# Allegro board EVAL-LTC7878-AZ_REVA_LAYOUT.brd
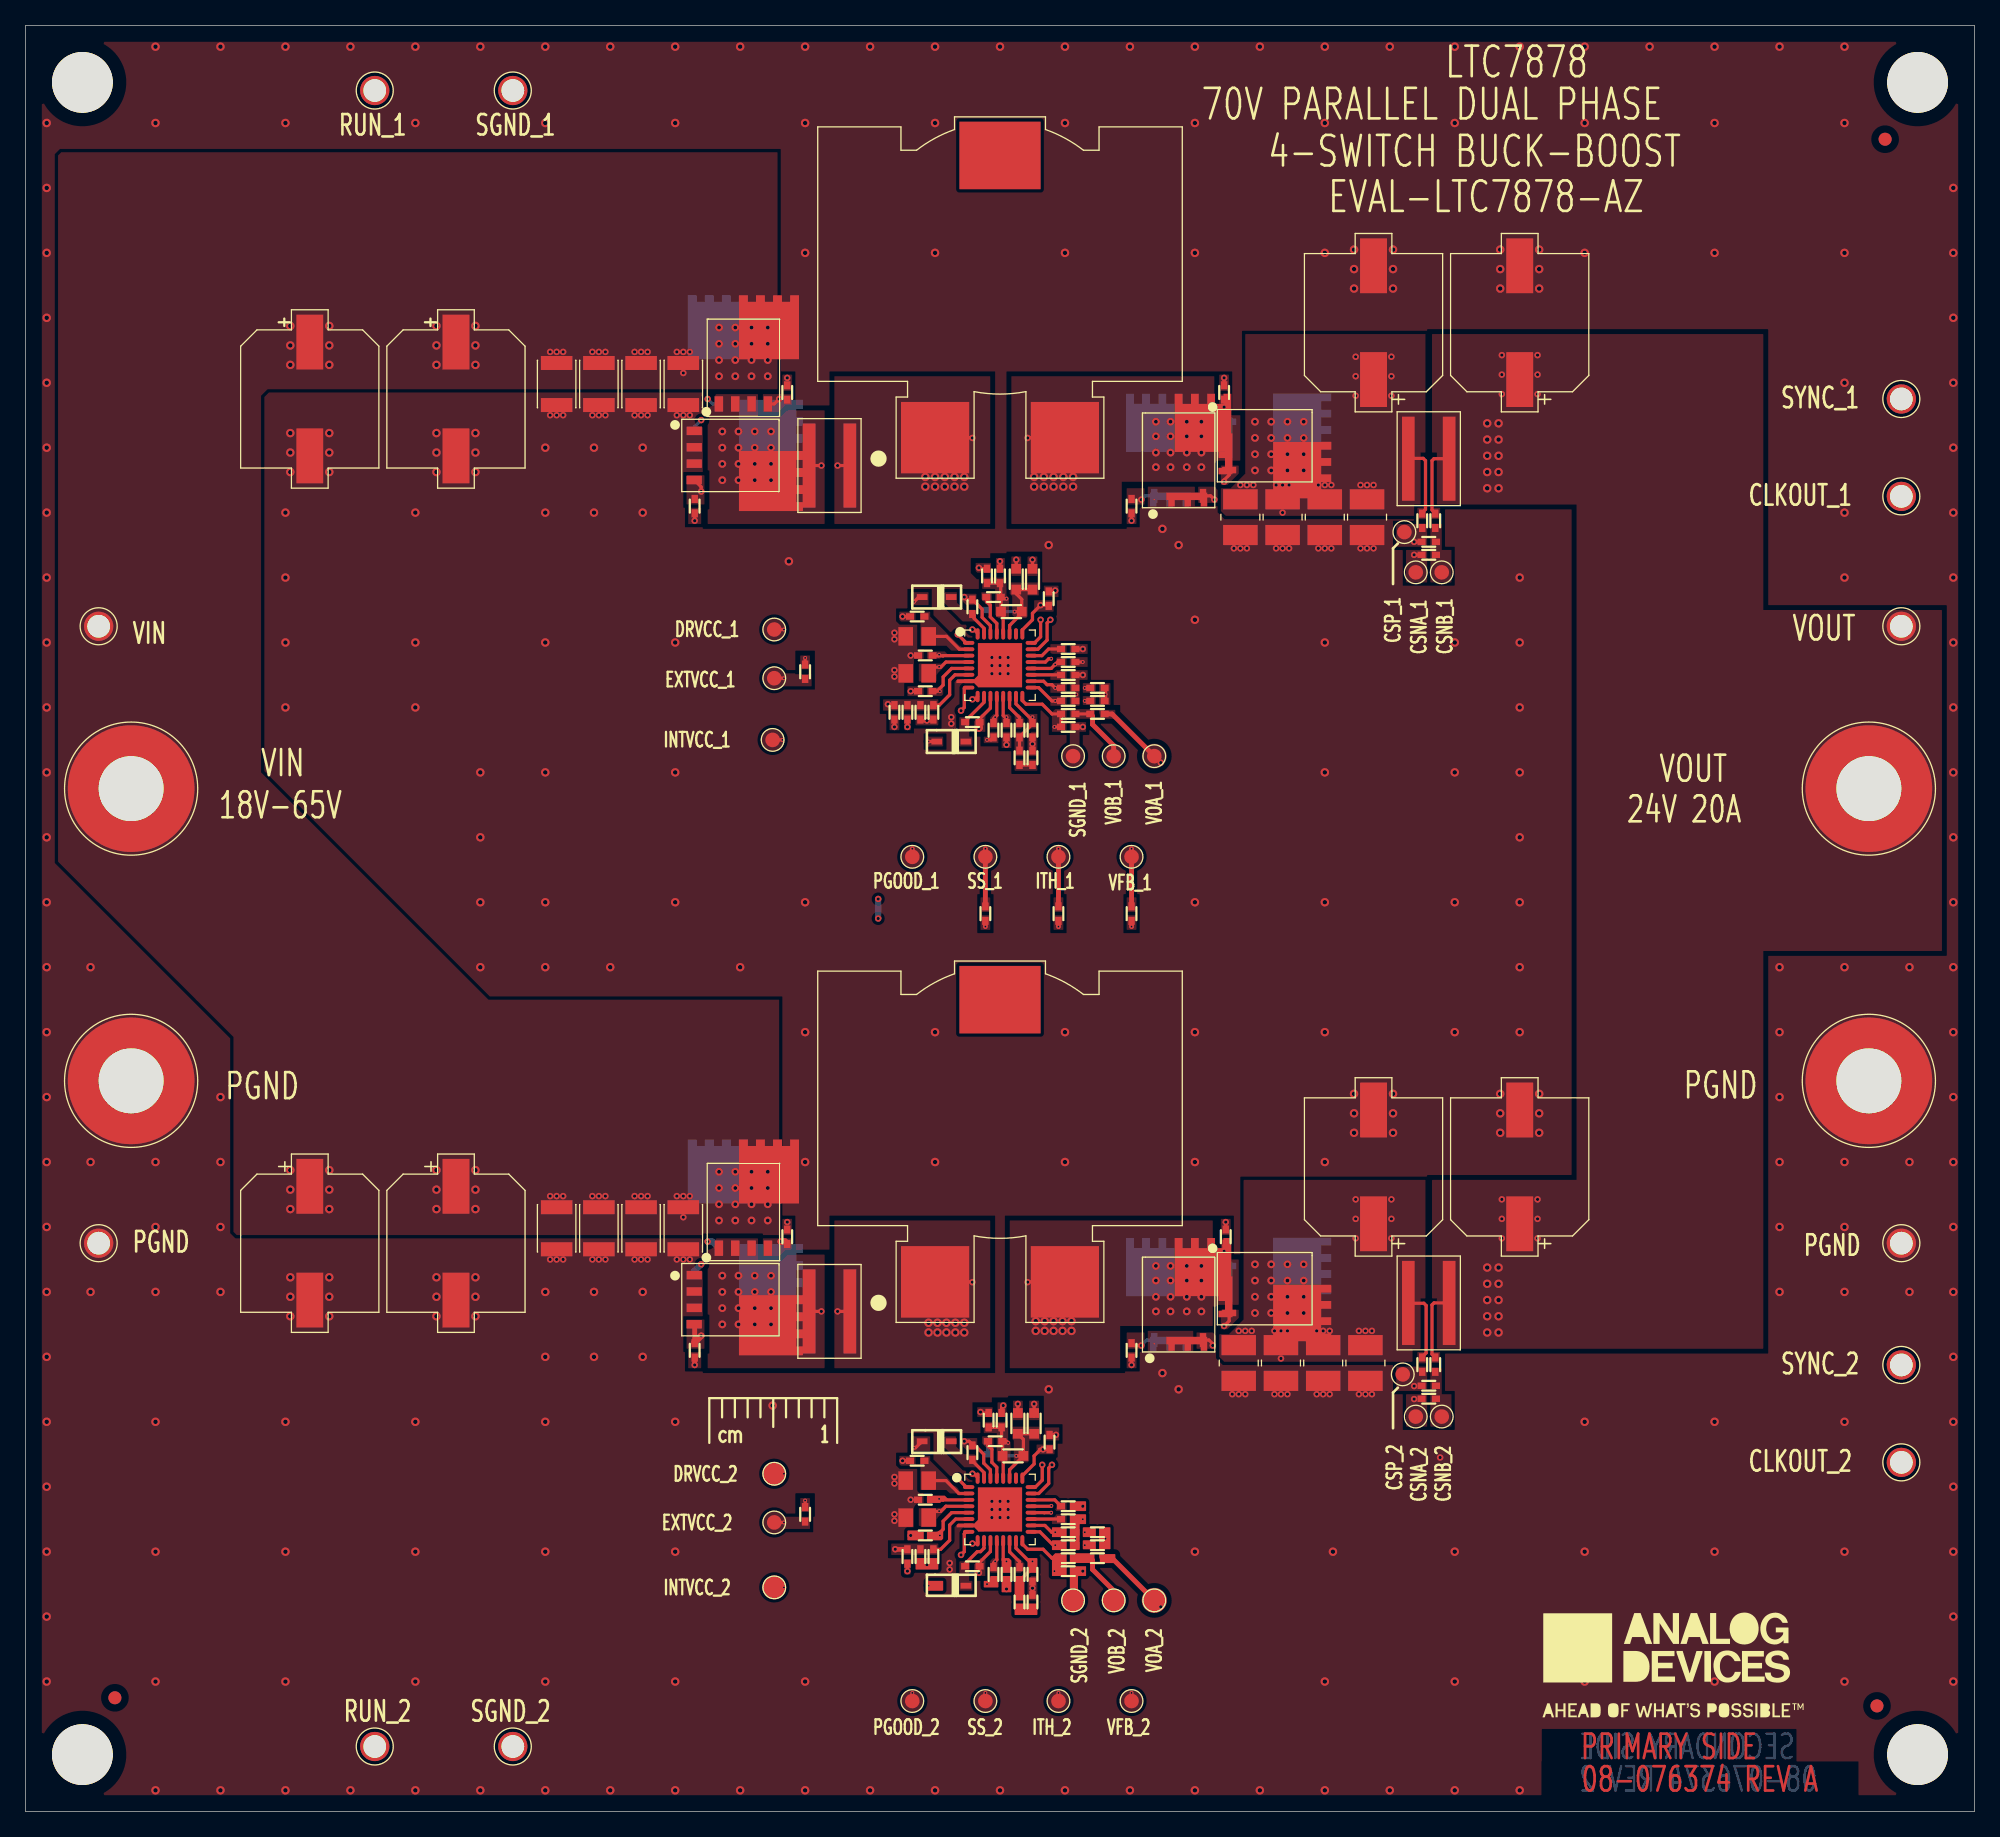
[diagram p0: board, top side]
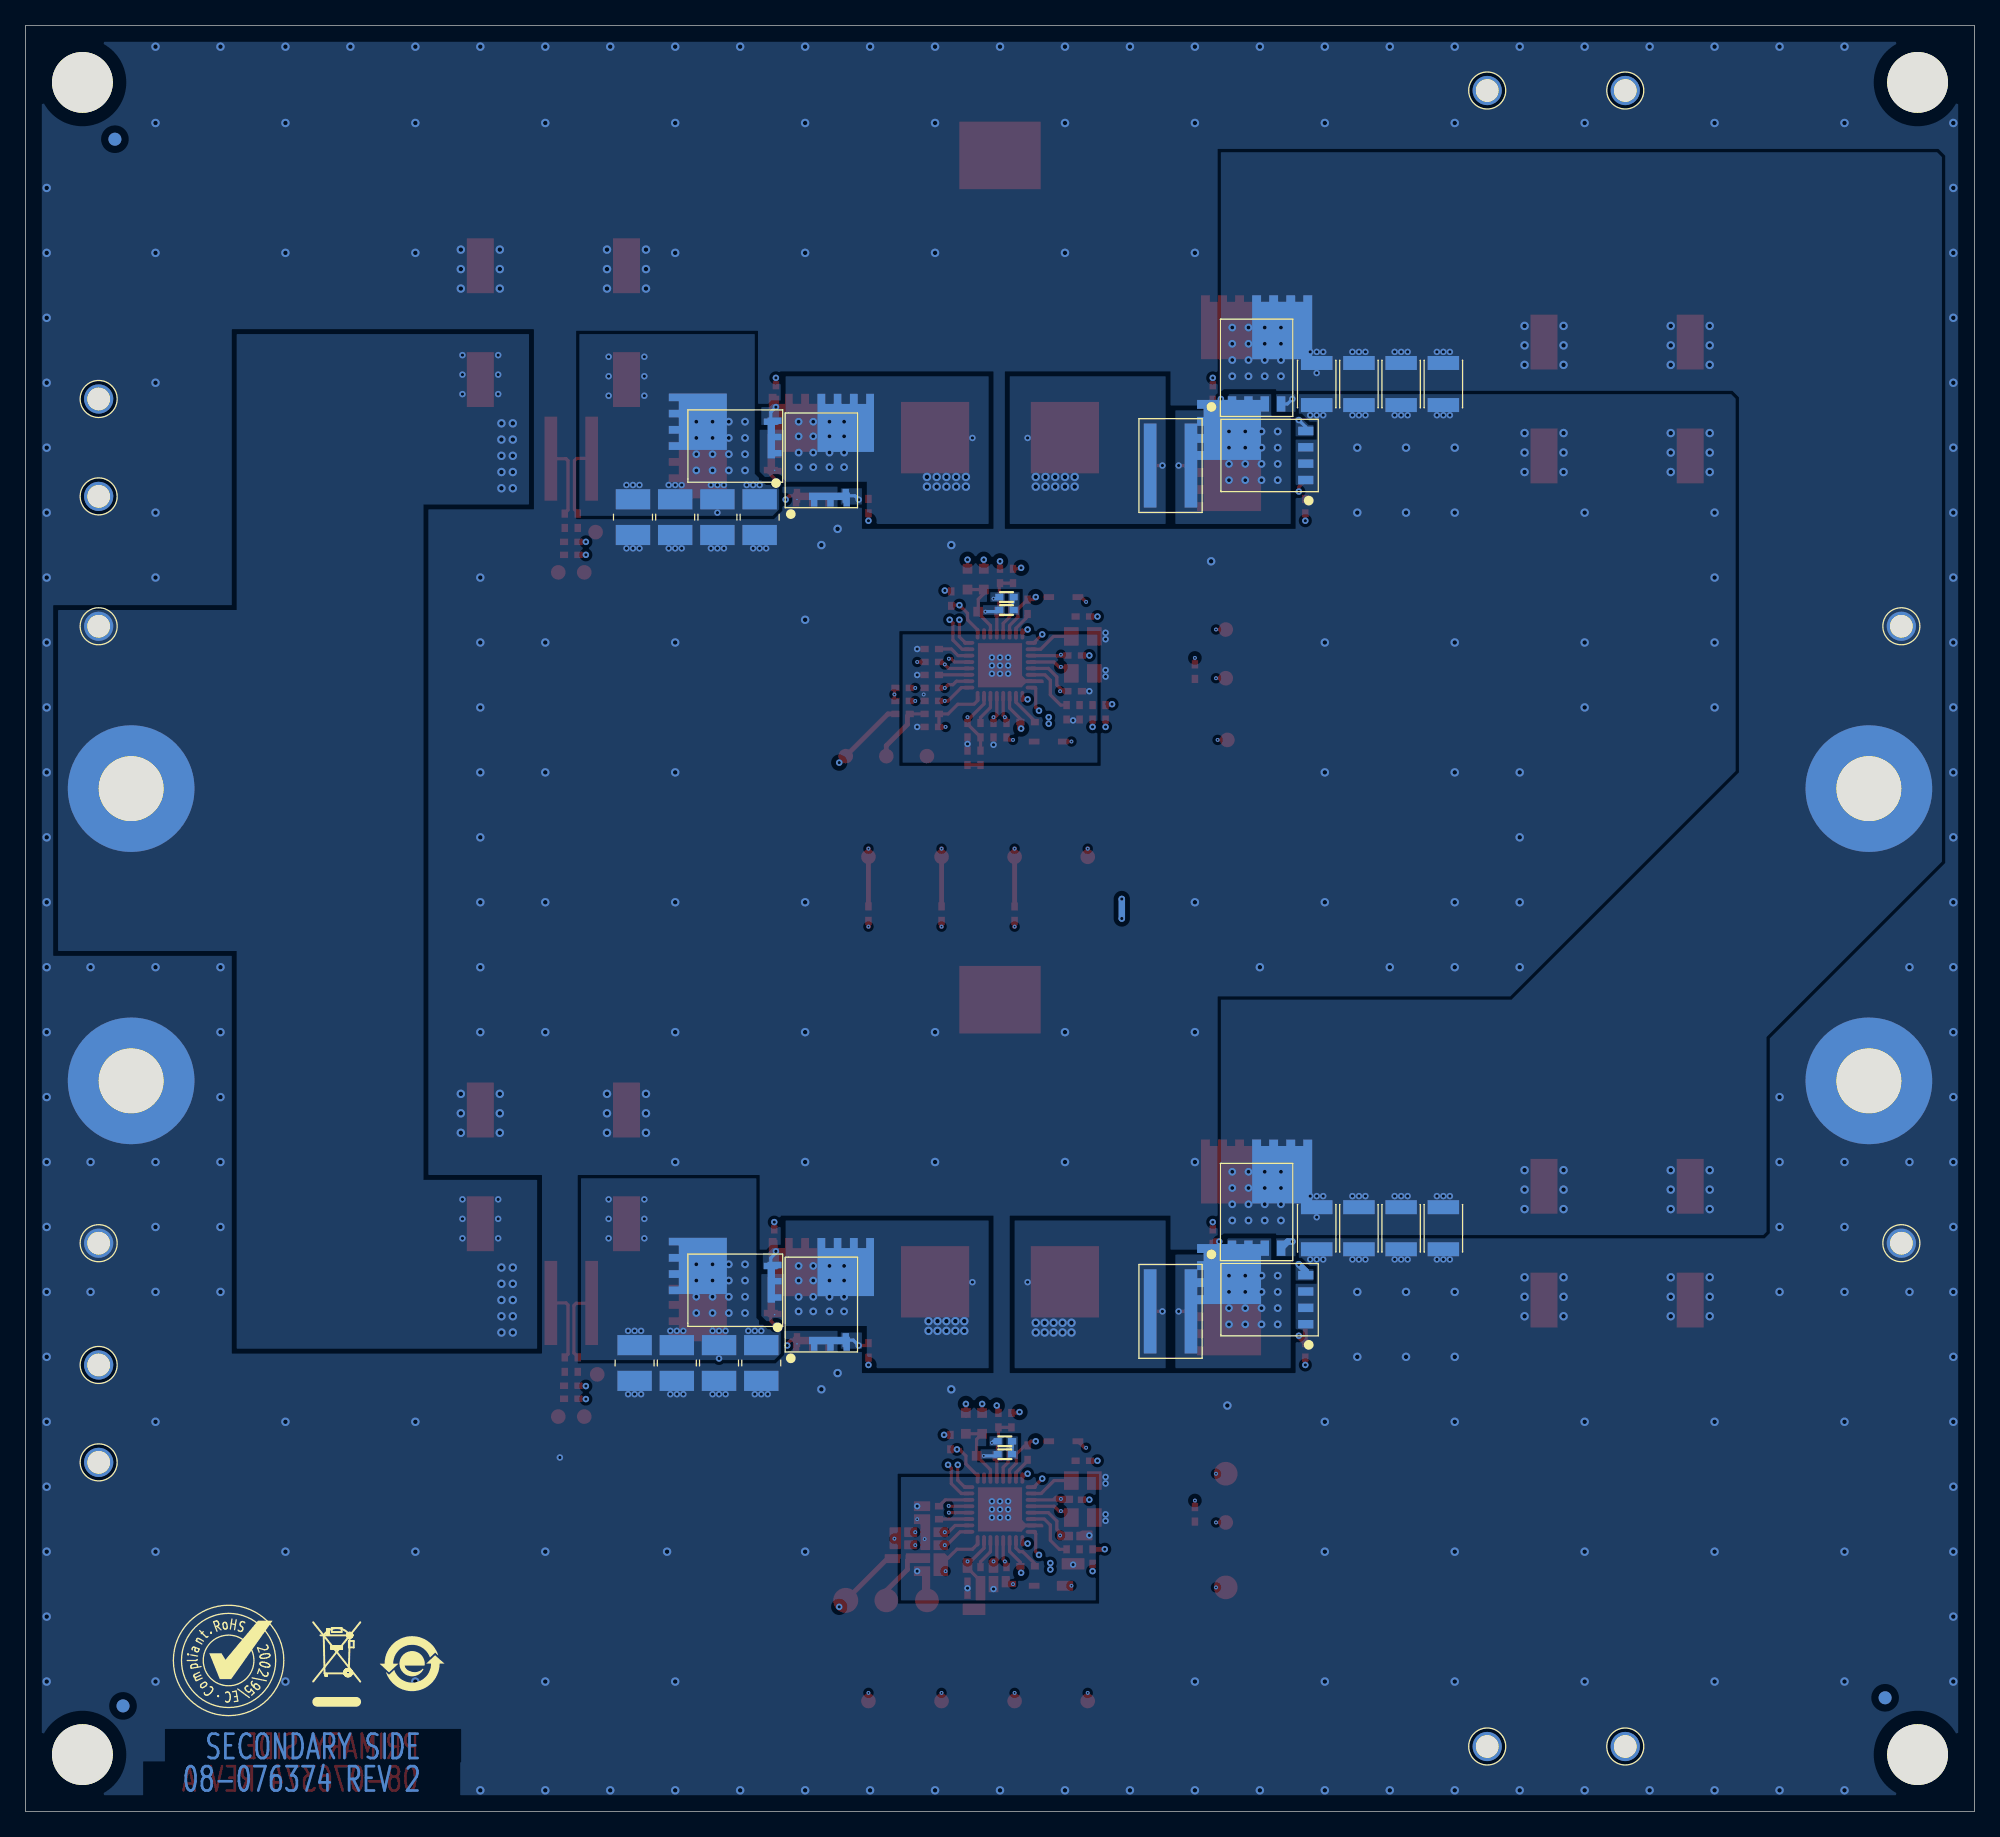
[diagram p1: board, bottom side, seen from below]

Outline 152.4 x 139.7 mm; copper layers: TOP, LAYER_2, LAYER_3, LAYER_4, LAYER_5, BOTTOM. Coordinates in mm from the lower left corner of the outline.
Outline path: 0,139.7 0,0 152.4,0 152.4,139.7 0,139.7

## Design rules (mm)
constraint set DEFAULT: min track width 0.254

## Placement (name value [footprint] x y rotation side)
C1  33uF  [CPLSMSQ406H413]  22.23 110.49 270 top
C2  33uF  [CPLSMSQ406H413]  33.66 110.49 270 top
C3  4.7uF  [C1210H87]  41.53 111.66 270 top
C4  4.7uF  [C1210H87]  44.83 111.66 270 top
C5  4.7uF  [C1210H87]  51.44 111.66 270 top
C6  4.7uF  [C1210H87]  48.13 111.66 270 top
C7  4.7uF  [C1210H87]  41.53 111.66 270 bottom
C8  4.7uF  [C1210H87]  44.83 111.66 270 bottom
C9  4.7uF  [C1210H87]  48.13 111.66 270 bottom
C10  4.7uF  [C1210H87]  51.44 111.66 270 bottom
C11  0.1UF  [C0402]  76.71 84.58 270 top
C12  1UF  [C0805H55]  69.72 91.92 180 top
C13  TBD0402  [C0402]  70.99 85.98 270 top
C14  100PF  [C0402]  78.74 84.58 270 top
C15  0.033UF  [C0402]  78.74 82.42 90 top
C16  1uF  [C0402]  74.04 94.23 90 top
C17  TBD0402  [C0402]  75.69 95 0 top
C18  6800pF  [C0603]  77.09 93.85 0 top
C19  1uF  [C0402]  74.04 85.22 180 top
C20  1UF  [C0805H55]  69.72 89.03 180 top
C21  4.7uF  [C0402]  70.36 87.63 180 top
C22  TBD0402  [C0402]  109.73 99.31 0 top
C23  4.7uF  [C0402]  70.36 90.42 180 top
C24  10uF  [C1210-2]  95 101.25 270 top
C25  10uF  [C1210-2]  98.3 101.25 270 top
C26  10uF  [C1210-2]  101.6 101.25 270 top
C27  10uF  [C1210-2]  104.9 101.25 270 top
C28  10uF  [C1210-2]  95 101.25 270 bottom
C29  10uF  [C1210-2]  98.3 101.25 270 bottom
C30  10uF  [C1210-2]  101.6 101.25 270 bottom
C31  10uF  [C1210-2]  104.9 101.25 270 bottom
C32  220UF  [CPLSMSQ406H413]  116.84 116.46 90 top
C33  220UF  [CPLSMSQ406H413]  105.41 116.46 90 top
C34  33uF  [CPLSMSQ406H413]  22.23 44.45 270 top
C35  33uF  [CPLSMSQ406H413]  33.66 44.45 270 top
C36  4.7uF  [C1210H87]  48.13 45.62 270 top
C37  4.7uF  [C1210H87]  51.44 45.62 270 bottom
C38  4.7uF  [C1210H87]  48.13 45.62 270 bottom
C39  4.7uF  [C1210H87]  41.53 45.62 270 top
C40  4.7uF  [C1210H87]  51.44 45.62 270 top
C41  4.7uF  [C1210H87]  44.83 45.62 270 top
C42  4.7uF  [C1210H87]  41.53 45.62 270 bottom
C43  4.7uF  [C1210H87]  44.83 45.62 270 bottom
C44  0.1UF  [C0402]  76.71 18.54 270 top
C45  1UF  [C0805H55]  69.72 25.88 180 top
C46  TBD0402  [C0402]  70.99 19.94 270 top
C47  100PF  [C0402]  78.74 18.54 270 top
C48  0.033UF  [C0402]  78.74 16.38 90 top
C49  1uF  [C0402]  74.04 28.07 90 top
C50  TBD0402  [C0402]  75.82 28.96 0 top
C51  6800pF  [C0603]  77.22 27.81 0 top
C52  1uF  [C0402]  74.04 19.18 180 top
C53  1UF  [C0805H55]  69.72 22.99 180 top
C54  4.7uF  [C0402]  70.36 21.59 180 top
C55  TBD0402  [C0402]  109.73 33.3 0 top
C56  4.7uF  [C0402]  70.36 24.38 180 top
C57  10uF  [C1210-2]  104.78 35.08 270 bottom
C58  10uF  [C1210-2]  101.47 35.08 270 bottom
C59  10uF  [C1210-2]  104.78 35.08 270 top
C60  10uF  [C1210-2]  101.47 35.08 270 top
C61  10uF  [C1210-2]  98.17 35.08 270 bottom
C62  10uF  [C1210-2]  98.17 35.08 270 top
C63  10uF  [C1210-2]  94.87 35.08 270 bottom
C64  10uF  [C1210-2]  94.87 35.08 270 top
C65  220UF  [CPLSMSQ406H413]  116.84 50.42 90 top
C66  220UF  [CPLSMSQ406H413]  105.41 50.42 90 top
D1  BAT46WJ,115  [SOD323F]  71.25 95 180 top
D2  BAT46WJ,115  [SOD323F]  72.39 83.69 180 top
D3  BAT46WJ,115  [SOD323F]  71.25 28.96 180 top
D4  BAT46WJ,115  [SOD323F]  72.39 17.65 180 top
J1  CKFH1032-10  [CNCFCKFH1032-10]  8.26 80.01 0 top
J2  CKFH1032-10  [CNCFCKFH1032-10]  8.26 57.15 0 top
J3  CKFH1032-10  [CNCFCKFH1032-10]  144.15 80.01 0 top
J4  CKFH1032-10  [CNCFCKFH1032-10]  144.15 57.15 0 top
L1  15UH  [LSML1102W764H728]  76.2 119.03 0 top
L2  15UH  [LSML1102W764H728]  76.2 52.99 0 top
M1  BSC030N08NS5ATMA1  [SON8]  56.13 112.93 0 top
M2  BSC030N08NS5ATMA1  [SON8]  55.12 106.07 270 top
M3  BSC005N03LS5ATMA1  [SON8_FL]  90.17 105.69 0 top
M4  BSC005N03LS5ATMA1  [SON8_FL]  96.9 106.83 270 top
M5  BSC030N08NS5ATMA1  [SON8]  56.13 112.93 180 bottom
M6  BSC030N08NS5ATMA1  [SON8]  55.12 106.07 90 bottom
M7  BSC005N03LS5ATMA1  [SON8_FL]  90.17 105.69 180 bottom
M8  BSC005N03LS5ATMA1  [SON8_FL]  96.9 106.81 90 bottom
M9  BSC030N08NS5ATMA1  [SON8]  56.13 46.89 0 top
M10  BSC030N08NS5ATMA1  [SON8]  55.12 40.03 270 top
M11  BSC005N03LS5ATMA1  [SON8_FL]  90.17 39.65 0 top
M12  BSC005N03LS5ATMA1  [SON8_FL]  96.9 40.89 270 top
M13  BSC030N08NS5ATMA1  [SON8]  56.13 46.89 180 bottom
M14  BSC030N08NS5ATMA1  [SON8]  55.12 40.03 90 bottom
M15  BSC005N03LS5ATMA1  [SON8_FL]  90.17 39.65 180 bottom
M16  BSC005N03LS5ATMA1  [SON8_FL]  96.9 40.77 90 bottom
NOREF  -  [unnamed]  147.96 135.25 180 top
NOREF#2  -  [#2]  53.47 28.83 0 top
NOREF#3  -  [#2]  -76.2 -76.2 0 top
NOREF#4  -  [#2]  81.92 146.05 0 top
NOREF#5  -  [#2]  244.35 286 0 top
NOREF#6  -  [#2]  63.5 63.5 180 top
NOREF#7  -  [#2]  289.43 215.01 0 top
NOREF#8  -  [#2]  -222.25 -146.05 0 top
NOREF#9  -  [#2]  308.36 156.46 0 top
NOREF#10  -  [#2]  -76.2 -76.2 0 top
NOREF#11  -  [#2]  63.5 0 90 top
NOREF#12  -  [#2]  128.27 11.43 0 top
NOREF#13  -  [#2]  152.4 0 90 top
NOREF#14  -  [#2]  132.84 5.71 270 top
NOREF#15  -  [unnamed]  145.41 130.81 0 top
NOREF#16  -  [unnamed]  4.45 4.45 180 top
NOREF#17  -  [#2]  -222.25 -146.05 0 top
NOREF#18  -  [#2]  0 139.7 0 top
NOREF#19  -  [#2]  -28.7 260.99 0 top
NOREF#20  -  [#2]  -76.2 -76.2 0 top
NOREF#21  -  [#2]  249.05 252.09 0 top
NOREF#22  -  [unnamed]  144.78 8.26 0 top
NOREF#23  -  [unnamed]  4.45 135.25 180 top
NOREF#24  -  [unnamed]  147.96 4.45 180 top
NOREF#25  -  [unnamed]  6.99 8.89 0 top
NOREF#26  -  [#2]  0 0 0 top
NOREF#27  -  [#2]  0 63.5 270 top
NOREF#28  -  [unnamed]  6.99 8.89 180 bottom
NOREF#29  -  [unnamed]  144.78 8.26 180 bottom
NOREF#30  -  [#2]  122.17 11.56 180 bottom
NOREF#31  -  [unnamed]  145.41 130.81 180 bottom
NOREF#32  -  [#2]  136.53 11.81 180 bottom
NOREF#33  -  [#2]  128.27 8.26 180 bottom
R1  0  [R0402]  81.53 89.92 0 top
R2  0  [R0402]  67.94 85.98 270 top
R3  0  [R0402]  75.06 70.23 270 top
R4  0  [R0402]  80.77 70.23 270 top
R5  0  [R0402]  86.49 70.23 270 top
R6  1  [R0402]  69.72 27.43 0 top
R7  301K  [R0402]  68.96 85.98 90 top
R8  21.5K  [R0402]  69.98 85.98 90 top
R9  0  [R0402]  59.56 111 90 top
R10  0  [R0402]  52.32 102.11 270 top
R11  0  [R0402]  77.72 84.58 90 top
R12  5.1K  [R0402]  77.72 82.42 270 top
R13  0  [R0402]  75.18 96.65 270 top
R14  0.005  [R1225H28]  62.87 105.28 0 top
R15  0.005  [R1225H28]  62.87 105.28 0 bottom
R16  49.9  [R0603]  77.47 96.39 270 top
R17  0  [R0402]  75.69 95 0 bottom
R18  56.2K  [R0402]  81.53 88.9 0 top
R19  TBD0402  [R0402]  76.2 96.65 270 top
R20  TBD0402  [R0402]  81.53 90.93 0 top
R21  TBD0402  [R0402]  75.69 93.98 0 bottom
R22  0  [R0402]  81.53 86.87 0 top
R23  TBD0603  [R0603]  78.74 96.39 270 top
R24  0  [R0402]  81.53 87.88 0 top
R25  TBD0402  [R0402]  83.82 87.88 0 top
R26  TBD0402  [R0402]  83.82 86.87 0 top
R27  100K  [R0402]  75.69 84.58 270 top
R28  0  [R0402]  86.49 102.11 270 top
R29  0  [R0402]  109.73 98.3 0 top
R30  0  [R0402]  93.73 111 90 top
R31  0  [R0402]  109.22 100.97 90 top
R32  0  [R0402]  110.24 100.97 90 top
R33  0  [R1225H28]  109.73 105.82 0 top
R34  0  [R0402]  83.82 85.85 180 top
R35  232K  [R0402]  81.53 85.85 180 top
R36  10K  [R0402]  81.53 84.84 0 top
R37  301K  [R0402]  68.96 19.94 90 top
R38  21.5K  [R0402]  69.98 19.94 90 top
R39  0  [R0402]  59.56 44.96 90 top
R40  0  [R0402]  52.32 36.07 270 top
R41  0  [R0402]  77.72 18.54 90 top
R42  5.1K  [R0402]  77.72 16.38 270 top
R43  0  [R0402]  75.31 30.61 270 top
R44  0.005  [R1225H28]  62.87 39.12 0 top
R45  0.005  [R1225H28]  62.87 39.12 0 bottom
R46  49.9  [R0603]  77.6 30.35 270 top
R47  0  [R0402]  75.82 28.96 0 bottom
R48  56.2K  [R0402]  81.53 22.86 0 top
R49  TBD0402  [R0402]  76.33 30.61 270 top
R50  TBD0402  [R0402]  81.53 23.88 0 top
R51  TBD0402  [R0402]  75.82 27.94 0 bottom
R52  0  [R0402]  81.53 20.83 0 top
R53  TBD0603  [R0603]  78.87 30.35 270 top
R54  0  [R0402]  81.53 21.84 0 top
R55  TBD0402  [R0402]  83.82 21.84 0 top
R56  TBD0402  [R0402]  83.82 20.83 0 top
R57  100K  [R0402]  75.69 18.54 270 top
R58  0  [R0402]  86.49 36.07 270 top
R59  0  [R0402]  109.73 32.28 0 top
R60  0  [R0402]  93.85 44.96 90 top
R61  0  [R0402]  109.22 34.95 90 top
R62  0  [R0402]  110.24 34.95 90 top
R63  0  [R1225H28]  109.73 39.78 0 top
R64  0  [R0402]  83.82 19.81 180 top
R65  232K  [R0402]  81.53 19.81 180 top
R66  10K  [R0402]  81.53 18.8 0 top
R67  1  [R0402]  60.96 23.24 270 top
R68  5.1  [R0402]  80.07 28.89 90 top
R69  1  [R0402]  69.72 93.47 0 top
R70  1  [R0402]  60.96 89.15 270 top
R71  5.1  [R0402]  80.01 94.87 90 top
TP1  2308-2-00-80-00-00-07-0  [CNMILLMAX2308]  5.71 92.71 0 top
TP4  2308-2-00-80-00-00-07-0  [CNMILLMAX2308]  5.71 44.45 0 top
TP5  2308-2-00-80-00-00-07-0  [CNMILLMAX2308]  27.3 134.62 0 top
TP6  2308-2-00-80-00-00-07-0  [CNMILLMAX2308]  38.1 134.62 0 top
TP7  2308-2-00-80-00-00-07-0  [CNMILLMAX2308]  146.69 110.49 0 top
TP8  2308-2-00-80-00-00-07-0  [CNMILLMAX2308]  146.69 102.87 0 top
TP9  TESTPAD  [TPSMC40]  75.06 74.68 0 top
TP10  TESTPAD  [TPSMC40]  80.77 74.68 0 top
TP11  TESTPAD  [TPSMC40]  108.71 96.93 0 top
TP12  TESTPAD  [TPSMC40]  58.55 88.65 0 top
TP13  TESTPAD  [TPSMC40]  110.74 96.93 0 top
TP14  TESTPAD  [TPSMC40]  58.42 83.82 0 top
TP15  TESTPAD  [TPSMC40]  69.34 74.68 0 top
TP16  TESTPAD  [TPSMC40]  107.82 100.08 0 top
TP17  TESTPAD  [TPSMC40]  58.55 92.46 0 top
TP18  TESTPAD  [TPSMC40]  86.49 74.68 0 top
TP19  TESTPAD  [TPSMC40]  88.27 82.55 0 top
TP20  TESTPAD  [TPSMC40]  85.09 82.55 0 top
TP21  TESTPAD  [TPSMC40]  81.92 82.55 0 top
TP22  2308-2-00-80-00-00-07-0  [CNMILLMAX2308]  146.69 92.71 0 top
TP25  2308-2-00-80-00-00-07-0  [CNMILLMAX2308]  146.69 44.45 0 top
TP30  2308-2-00-80-00-00-07-0  [CNMILLMAX2308]  27.3 5.08 0 top
TP31  2308-2-00-80-00-00-07-0  [CNMILLMAX2308]  38.1 5.08 0 top
TP32  2308-2-00-80-00-00-07-0  [CNMILLMAX2308]  146.69 34.92 0 top
TP33  2308-2-00-80-00-00-07-0  [CNMILLMAX2308]  146.69 27.3 0 top
TP34  TESTPAD  [TPSMC40]  75.06 8.64 0 top
TP35  TESTPAD  [TPSMC40]  80.77 8.64 0 top
TP36  TESTPAD  [TPSMC40]  108.71 30.89 0 top
TP37  TESTPAD  [TPSMC40]  58.55 22.61 0 top
TP38  TESTPAD  [TPSMC40]  110.74 30.89 0 top
TP39  TESTPAD  [TPSMC40]  58.55 17.53 0 top
TP40  TESTPAD  [TPSMC40]  69.34 8.64 0 top
TP41  TESTPAD  [TPSMC40]  107.7 34.19 0 top
TP42  TESTPAD  [TPSMC40]  58.55 26.42 0 top
TP43  TESTPAD  [TPSMC40]  86.49 8.64 0 top
TP44  TESTPAD  [TPSMC40]  88.27 16.51 0 top
TP45  TESTPAD  [TPSMC40]  85.09 16.51 0 top
TP46  TESTPAD  [TPSMC40]  81.92 16.51 0 top
U1  LTC7878AUH#TRPBF  [QFN32_5X5_PAD3_45X3_45_05-08-1693]  76.2 89.66 270 top
U2  LTC7878AUH#TRPBF  [QFN32_5X5_PAD3_45X3_45_05-08-1693]  76.2 23.62 270 top

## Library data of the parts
C1 C2 C34 C35 = CAPP: User Part Number: UPN; Tolerance: 20; alternate symbols: (CPLSMSQ406H413); part number: CAPP_SM-33UF,80V,20,E039984,CPLSMSQ406H413; tolerance: 20
C3-C10 C36-C43 = CAP: Tolerance: 10; User Part Number: UPN; alternate symbols: (C1210H87); part number: CAP_SM-4.7UF,100V,10,E033812,C1210H87; tolerance: 10
C11 C44 = CAP: Tolerance: 10; User Part Number: UPN; alternate symbols: (C0402); part number: CAP_SM-0.1UF,10V,10,E042769,C0402; tolerance: 10
C12 C20 C45 C53 = CAP: User Part Number: UPN; Tolerance: 10; alternate symbols: (C0805H55); part number: CAP_SM-1UF,100V,10,E048499,C0805H55; tolerance: 10
C13 C17 C22 C46 C50 C55 = CAP: User Part Number: UPN; alternate symbols: (C0402); part number: CAP_SM-TBD0402,TBD0402,TBD0402,E000381,C0402
C14 C47 = CAP: Tolerance: 20; User Part Number: UPN; alternate symbols: (C0402); part number: CAP_SM-100PF,10V,20,E062219,C0402; tolerance: 20
C15 C48 = CAP: Tolerance: 10; User Part Number: UPN; alternate symbols: (C0402); part number: CAP_SM-0.033UF,16V,10,E000292,C0402; tolerance: 10
C16 C19 C49 C52 = CAP: Tolerance: 10; User Part Number: UPN; alternate symbols: (C0402); part number: CAP_SM-1UF,16V,10,E019219,C0402; tolerance: 10
C18 C51 = CAP: Tolerance: 10; User Part Number: UPN; alternate symbols: (C0603); part number: CAP_SM-6800PF,50V,10,E007966,C0603; tolerance: 10
C21 C23 C54 C56 = CAP: Tolerance: 10; User Part Number: UPN; alternate symbols: (C0402); part number: CAP_SM-4.7UF,10V,10,E028571,C0402; tolerance: 10
C24-C31 C57-C64 = CAP: Tolerance: 10; User Part Number: UPN; alternate symbols: (C1210-2); part number: CAP_SM-10UF,50V,10,E022361,C1210-2; tolerance: 10
C32 C33 C65 C66 = CAPP: User Part Number: UPN; Tolerance: 20%; alternate symbols: (CPLSMSQ406H413); part number: CAPP_SM-220UF,35V,20%,E062218,CPLSMSQ406H413; tolerance: 20%
D1-D4 = DIOSCHOTTKY: Tolerance: N/A; User Part Number: UPN; alternate symbols: (SOD323F); part number: DIOSCHOTTKY_SM-BAT46WJ,115,100V,N/A,E016832,SOD323F; tolerance: N/A
J1-J4 = CNTP1P: Tolerance: N/A; User Part Number: UPN; alternate symbols: (CNCFCKFH1032-10_C380D200); part number: CNTP1P_TH-CKFH1032-10,E050511,CNCFCKFH1032-10; tolerance: N/A
L1 L2 = IND: User Part Number: UPN; Tolerance: 15; alternate symbols: (LSML1102W764H728); part number: IND_SM-15UH,15,E061087,LSML1102W764H728; tolerance: 15
M1 M2 M5 M6 M9 M10 M13 M14 = TRANNMOSFET_V15: Tolerance: N/A; User Part Number: UPN; alternate symbols: (SON8); part number: TRANNMOSFET_V15_SM-BSC030N08NS5ATMA1,E043910,SON8; tolerance: N/A
M3 M4 M7 M8 M11 M12 M15 M16 = TRANNMOSFET8P: Tolerance: N/A; User Part Number: UPN; alternate symbols: (SON8_FL); part number: TRANNMOSFET8P_SM-BSC005N03LS5ATMA1,E062160,SON8_FL; tolerance: N/A
R1-R5 R9-R11 R13 R17 R22 R24 R28-R32 R34 R39-R41 R43 R47 R52 R54 R58-R62 R64 = RES: Tolerance: JUMPER; User Part Number: UPN; alternate symbols: (R0402); part number: RES_SM-0,E003438,1/10W,JUMPER,R0402; tolerance: JUMPER
R6 R67 R69 R70 = RES: Tolerance: 5; User Part Number: UPN; alternate symbols: (R0402); part number: RES_SM-1,E010031,1/10W,5,R0402; tolerance: 5
R7 R37 = RES: Tolerance: 1; User Part Number: UPN; alternate symbols: (R0402); part number: RES_SM-301K,E020913,1/10W,1,R0402; tolerance: 1
R8 R38 = RES: Tolerance: 1; User Part Number: UPN; alternate symbols: (R0402); part number: RES_SM-21.5K,E017474,1/10W,1,R0402; tolerance: 1
R12 R42 = RES: Tolerance: 1; User Part Number: UPN; alternate symbols: (R0402); part number: RES_SM-5.1K,E019615,1/16W,1,R0402; tolerance: 1
R14 R15 R44 R45 = RES: User Part Number: UPN; Tolerance: 1; alternate symbols: (R1225H28); part number: RES_SM-0.005,E046964,3W,1,R1225H28; tolerance: 1
R16 R46 = RES: Tolerance: 1; User Part Number: UPN; alternate symbols: (R0603); part number: RES_SM-49.9,E003673,1/10W,1,R0603; tolerance: 1
R18 R48 = RES: Tolerance: 1; User Part Number: UPN; alternate symbols: (R0402); part number: RES_SM-56.2K,E003771,1/10W,1,R0402; tolerance: 1
R19-R21 R25 R26 R49-R51 R55 R56 = RES: User Part Number: UPN; alternate symbols: (R0402); part number: RES_SM-TBD0402,E004049,TBD0402,TBD0402,R0402
R23 R53 = RES: User Part Number: UPN; alternate symbols: (R0603); part number: RES_SM-TBD0603,E004050,TBD0603,TBD0603,R0603
R27 R57 = RES: Tolerance: 1; User Part Number: UPN; alternate symbols: (R0402); part number: RES_SM-100K,E003796,1/10W,1,R0402; tolerance: 1
R33 R63 = RES: User Part Number: UPN; Tolerance: N/A; alternate symbols: (R1225H28); part number: RES_SM-0,E048848,2W,N/A,R1225H28; tolerance: N/A
R35 R65 = RES: Tolerance: 1; User Part Number: UPN; alternate symbols: (R0402); part number: RES_SM-232K,E006802,1/10W,1,R0402; tolerance: 1
R36 R66 = RES: Tolerance: 1; User Part Number: UPN; alternate symbols: (R0402); part number: RES_SM-10K,E003751,1/10W,1,R0402; tolerance: 1
R68 R71 = RES: Tolerance: 5; User Part Number: UPN; alternate symbols: (R0402); part number: RES_SM-5.1,E017500,1/10W,5,R0402; tolerance: 5
TP1 TP4-TP8 TP22 TP25 TP30-TP33 = CNTP1P: User Part Number: UPN; Tolerance: N/A; alternate symbols: (CNMILLMAX2308); part number: CNTP1P_TH-2308-2-00-80-00-00-07-0,E030692,CNMILLMAX2308; tolerance: N/A
TP9-TP21 TP34-TP46 = NCTESTPAD: Tolerance: N/A; User Part Number: UPN; alternate symbols: (TPSMC40); part number: NCTESTPAD_SM-TESTPAD,E019801,TPSMC40; tolerance: N/A
U1 U2 = ADLTC7878: User Part Number: UPN; Tolerance: N/A; alternate symbols: (QFN32_5X5_PAD3_45X3_45_05-08-1693); part number: ADLTC7878_SM-LTC7878AUH#TRPBF,E062157,QFN32_5X5_PAD3_45X3_45_05-08-1693; tolerance: N/A

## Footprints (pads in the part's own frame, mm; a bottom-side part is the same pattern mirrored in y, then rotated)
C0402
  rect 0.635x0.508 smd: 1(-0.564,0) 2(0.564,0)
C0603
  rect 0.762x0.762 smd: 1(-0.813,0) 2(0.813,0)
C0805H55
  rect 1.143x1.448 smd: 1(-0.9,0) 2(0.9,0)
C1210-2
  rect 1.575x2.692 smd: 1(-1.397,0) 2(1.397,0)
C1210H87
  rect 1.092x2.464 smd: 1(-1.646,0) 2(1.646,0)
CNCFCKFH1032-10
  round 9.906 hole 5.08: 1(0,0)
CNMILLMAX2308
  round 2.286 hole 1.778: 1(0,0)
CPLSMSQ406H413
  rect 4.293x2.108 smd: N(4.45,0) P(-4.45,0)
LSML1102W764H728
  rect 6.35x5.283 smd: (0,10.514)
  rect 5.334x5.588 smd: 1(-5.075,-11.56) 2(5.075,-11.56)
QFN32_5X5_PAD3_45X3_45_05-08-1693
  oval 0.305x0.889 smd: 1(-1.75,-2.45) 2(-1.25,-2.45) 3(-0.75,-2.45) 4(-0.25,-2.45) 5(0.25,-2.45) 6(0.75,-2.45) 7(1.25,-2.45) 8(1.75,-2.45) 17(1.75,2.45) 18(1.25,2.45) 19(0.75,2.45) 20(0.25,2.45) 21(-0.25,2.45) 22(-0.75,2.45) 23(-1.25,2.45) 24(-1.75,2.45)
  oval 0.889x0.305 smd: 9(2.45,-1.75) 10(2.45,-1.25) 11(2.45,-0.75) 12(2.45,-0.25) 13(2.45,0.25) 14(2.45,0.75) 15(2.45,1.25) 16(2.45,1.75) 25(-2.45,1.75) 26(-2.45,1.25) 27(-2.45,0.75) 28(-2.45,0.25) 29(-2.45,-0.25) 30(-2.45,-0.75) 31(-2.45,-1.25) 32(-2.45,-1.75)
  rect 3.454x3.454 smd: 33(0,0)
R0402
  rect 0.635x0.508 smd: 1(-0.564,0) 2(0.564,0)
R0603
  rect 0.762x0.762 smd: 1(-0.813,0) 2(0.813,0)
R1225H28
  rect 0.991x6.579 smd: 1(-1.595,0) 2(1.595,0)
SOD323F
  rect 0.838x0.457 smd: A(1.14,0) C(-1.14,0)
SON8
  rect 0.66x1.194 smd: 1(-1.92,-2.828) 2(-0.64,-2.828) 3(0.64,-2.828) 4(1.92,-2.828)
  custom 1.175x1.175 smd: 5(2,3.171)
  round 0.127 smd: 6(0.678,3.211) 7(-0.68,3.236) 8(-2.002,3.223)
SON8_FL
  round 0.127 smd: 1(-1.905,-3.071) 2(-0.635,-3.071) 6(0.635,2.931) 7(-0.635,2.931) 8(-1.905,2.931)
  custom 0.273x0.273 smd: 3(0.635,-3.071)
  rect 0.508x1.092 smd: 4(1.905,-2.779)
  custom 1.105x1.105 smd: 5(1.905,2.931)
TPSMC40
  round 1.143 smd: 1(0,0)
unnamed
  round 4.75 hole 4.75 unplated: (0,0)

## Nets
SGND1: C11.2(N2) C13.2(N2) C14.2(N2) C15.2(N2) C21.2(N2) R8.1 R18.2(N2) R20.2(N2) R22.2(N2) R24.2(N2) R36.2(N2) TP6.1(N1) TP21.1(N1) U1.33
SGND2: C44.2(N2) C46.2(N2) C47.2(N2) C48.2(N2) C54.2(N2) R38.1 R48.2(N2) R50.2(N2) R52.2(N2) R54.2(N2) R66.2(N2) TP31.1(N1) TP46.1(N1) U2.33
VIN: C1.P C2.P C3.1 C4.1 C5.1 C6.1 C7.1 C8.1 C9.1 C10.1 C34.P C35.P C36.1 C37.1 C38.1 C39.1 C40.1 C41.1 C42.1 C43.1 J1.1(N1) M1.5 M1.6 M1.7 M1.8 M5.5 M5.6 M5.7 M5.8 M9.5 M9.6 M9.7 M9.8 M13.5 M13.6 M13.7 M13.8 R6.1 R7.1 R37.1 R69.1 TP1.1(N1)
CLKOUT_1: R1.1 TP8.1(N1) U1.20
CLKOUT_2: TP33.1(N1) U2.20
DRVCC_1: C23.1 D1.A(P) D2.A(P) TP17.1(N1) U1.3
DRVCC_2: C56.1 D3.A(P) D4.A(P) TP42.1(N1) U2.3
GROUND: C1.N(N2) C2.N(N2) C3.2(N2) C4.2(N2) C5.2(N2) C6.2(N2) C7.2(N2) C8.2(N2) C9.2(N2) C10.2(N2) C12.2(N2) C20.2(N2) C23.2(N2) C24.2(N2) C25.2(N2) C26.2(N2) C27.2(N2) C28.2(N2) C29.2(N2) C30.2(N2) C31.2(N2) C32.N(N2) C33.N(N2) C34.N(N2) C35.N(N2) C36.2(N2) C37.2(N2) C38.2(N2) C39.2(N2) C40.2(N2) C41.2(N2) C42.2(N2) C43.2(N2) C45.2(N2) C53.2(N2) C56.2(N2) C57.2(N2) C58.2(N2) C59.2(N2) C60.2(N2) C61.2(N2) C62.2(N2) C63.2(N2) C64.2(N2) C65.N(N2) C66.N(N2) J2.1(N1) J4.1(N1) M2.1 M2.2 M2.3(S3) M3.1 M3.2 M3.3(S3) M6.1 M6.2 M6.3(S3) M7.1 M7.2 M7.3(S3) M10.1 M10.2 M10.3(S3) M11.1 M11.2 M11.3(S3) M14.1 M14.2 M14.3(S3) M15.1 M15.2 M15.3(S3) TP4.1(N1) TP25.1(N1) U1.7 U2.7
INTVCC_1: C21.1 R25.2(N2) R26.2(N2) R27.2(N2) TP14.1(N1) U1.5
INTVCC_2: C54.1 R55.2(N2) R56.2(N2) R57.2(N2) TP39.1(N1) U2.5
ITH_1: C14.1 R4.1 R11.1 R12.1 TP10.1(N1) U1.15
ITH_2: C47.1 R4.2(N2) R41.1 R42.1 TP35.1(N1) U2.15
RUN_1: C13.1 R2.1 R7.2(N2) R8.2(N2) TP5.1(N1) U1.6
RUN_2: C46.1 R2.2(N2) R37.2(N2) R38.2(N2) TP30.1(N1) U2.6
SS_1: C11.1 R3.1 TP9.1(N1) U1.13
SS_2: C44.1 R3.2(N2) TP34.1(N1) U2.13
SYNC_1: TP7.1(N1) U1.21
SYNC_2: R1.2(N2) TP32.1(N1) U2.21
UNNAMED_1_ADLTC7878_I123_BG1: R40.2(N2) U2.1
UNNAMED_1_ADLTC7878_I123_BG2: R58.2(N2) U2.8
UNNAMED_1_ADLTC7878_I123_BOOST1: C49.1 D3.C U2.31
UNNAMED_1_ADLTC7878_I123_BOOST2: C52.2(N2) D4.C U2.10
UNNAMED_1_ADLTC7878_I123_CSN: R59.1 TP36.1(N1) U2.24
UNNAMED_1_ADLTC7878_I123_CSP: C55.1 R61.1 TP41.1(N1) U2.23
UNNAMED_1_ADLTC7878_I123_EXTVCC: C53.1 R67.1 U2.4
UNNAMED_1_ADLTC7878_I123_FREQ: R48.1 U2.19
UNNAMED_1_ADLTC7878_I123_ISNSD: C50.1 R47.1 R51.1 U2.29
UNNAMED_1_ADLTC7878_I123_ISNSN: C51.2(N2) R46.2(N2) R51.2(N2) R53.2(N2) U2.27
UNNAMED_1_ADLTC7878_I123_ISNSP: C50.2(N2) C51.1 R43.2(N2) R47.2(N2) R49.2(N2) U2.28
UNNAMED_1_ADLTC7878_I123_ITHB: R41.2(N2) U2.14
UNNAMED_1_ADLTC7878_I123_MODE: R52.1 R56.1 U2.17
UNNAMED_1_ADLTC7878_I123_PGOOD: R57.1 TP40.1(N1) U2.12
UNNAMED_1_ADLTC7878_I123_PHASMD: R54.1 R55.1 U2.18
UNNAMED_1_ADLTC7878_I123_SETCUR: R50.1 U2.22
UNNAMED_1_ADLTC7878_I123_SW1: C49.2(N2) M9.1 M9.2 M9.3(S3) M10.5 M10.6 M10.7 M10.8 M13.1 M13.2 M13.3(S3) M14.5 M14.6 M14.7 M14.8 R43.1 R44.1 R45.1 U2.30
UNNAMED_1_ADLTC7878_I123_SW2: C52.1 L2.2(N2) M11.5 M11.6 M11.7 M11.8 M12.1 M12.2 M12.3(S3) M15.5 M15.6 M15.7 M15.8 M16.1 M16.2 M16.3(S3) R53.1 U2.11
UNNAMED_1_ADLTC7878_I123_TG1: R39.2(N2) U2.32
UNNAMED_1_ADLTC7878_I123_TG2: R60.2(N2) U2.9
UNNAMED_1_ADLTC7878_I123_VIN: C45.1 R6.2(N2) U2.2
UNNAMED_1_ADLTC7878_I123_VOUT: R67.2(N2) R68.1 TP37.1(N1) U2.25(VOUT)
UNNAMED_1_CAP_I31_N1: C48.1 R42.2(N2)
UNNAMED_1_CAP_I88_N2: C55.2(N2) R59.2(N2) R62.1 TP38.1(N1)
UNNAMED_1_CAP_I107_N1: C57.1 C58.1 C59.1 C60.1 C61.1 C62.1 C63.1 C64.1 C66.P M12.5 M12.6 M12.7 M12.8 M16.5 M16.6 M16.7 M16.8 R61.2(N2) R63.1 R68.2(N2)
UNNAMED_1_IND_I80_N1: L2.1 R44.2(N2) R45.2(N2) R46.1 R49.1
UNNAMED_1_NCTESTPAD_I100_N1: R64.2(N2) R65.1 TP45.1(N1)
UNNAMED_1_RES_I60_N1: M9.4 M13.4 R39.1
UNNAMED_1_RES_I61_N1: M10.4 M14.4 R40.1
UNNAMED_1_RES_I75_N1: M11.4 M15.4 R58.1
UNNAMED_1_RES_I102_N1: M12.4 M16.4 R60.1
UNNAMED_2_ADLTC7878_I88_BG1: R10.2(N2) U1.1
UNNAMED_2_ADLTC7878_I88_BG2: R28.2(N2) U1.8
UNNAMED_2_ADLTC7878_I88_CSN: R29.1 TP11.1(N1) U1.24
UNNAMED_2_ADLTC7878_I88_CSP: C22.1 R31.1 TP16.1(N1) U1.23
UNNAMED_2_ADLTC7878_I88_EXTVCC: C20.1 R70.1 U1.4
UNNAMED_2_ADLTC7878_I88_FREQ: R18.1 U1.19
UNNAMED_2_ADLTC7878_I88_ISNSN: C18.2(N2) R16.2(N2) R21.2(N2) R23.2(N2) U1.27
UNNAMED_2_ADLTC7878_I88_ITHB: R11.2(N2) U1.14
UNNAMED_2_ADLTC7878_I88_MODE: R22.1 R26.1 U1.17
UNNAMED_2_ADLTC7878_I88_PGOOD: R27.1 TP15.1(N1) U1.12
UNNAMED_2_ADLTC7878_I88_PHASMD: R24.1 R25.1 U1.18
UNNAMED_2_ADLTC7878_I88_SETCUR: R20.1 U1.22
UNNAMED_2_ADLTC7878_I88_SW1: C16.2(N2) M1.1 M1.2 M1.3(S3) M2.5 M2.6 M2.7 M2.8 M5.1 M5.2 M5.3(S3) M6.5 M6.6 M6.7 M6.8 R13.1 R14.1 R15.1 U1.30
UNNAMED_2_ADLTC7878_I88_SW2: C19.1 L1.2(N2) M3.5 M3.6 M3.7 M3.8 M4.1 M4.2 M4.3(S3) M7.5 M7.6 M7.7 M7.8 M8.1 M8.2 M8.3(S3) R23.1 U1.11
UNNAMED_2_ADLTC7878_I88_TG1: R9.2(N2) U1.32
UNNAMED_2_ADLTC7878_I88_TG2: R30.2(N2) U1.9
UNNAMED_2_ADLTC7878_I88_VIN: C12.1 R69.2(N2) U1.2
UNNAMED_2_ADLTC7878_I88_VOUT: R70.2(N2) R71.1 TP12.1(N1) U1.25(VOUT)
UNNAMED_2_CAP_I49_N1: C17.1 R17.1 R21.1 U1.29
UNNAMED_2_CAP_I49_N2: C17.2(N2) C18.1 R13.2(N2) R17.2(N2) R19.2(N2) U1.28
UNNAMED_2_CAP_I57_N1: C15.1 R12.2(N2)
UNNAMED_2_CAP_I58_N1: C16.1 D1.C U1.31
UNNAMED_2_CAP_I59_N2: C19.2(N2) D2.C U1.10
UNNAMED_2_CAP_I132_N2: C22.2(N2) R29.2(N2) R32.1 TP13.1(N1)
UNNAMED_2_CAP_I188_N1: C24.1 C25.1 C26.1 C27.1 C28.1 C29.1 C30.1 C31.1 C33.P M4.5 M4.6 M4.7 M4.8 M8.5 M8.6 M8.7 M8.8 R31.2(N2) R33.1 R71.2(N2)
UNNAMED_2_IND_I44_N1: L1.1 R14.2(N2) R15.2(N2) R16.1 R19.1
UNNAMED_2_NCTESTPAD_I129_N1: R34.2(N2) R35.1 TP20.1(N1)
UNNAMED_2_RES_I34_N1: M2.4 M6.4 R10.1
UNNAMED_2_RES_I154_N1: M1.4 M5.4 R9.1
UNNAMED_2_TRANNMOSFET8P_I163_G: M3.4 M7.4 R28.1
UNNAMED_2_TRANNMOSFET8P_I168_G: M4.4 M8.4 R30.1
VFB_1: R5.1 R35.2(N2) R36.1 TP18.1(N1) U1.16
VFB_2: R5.2(N2) R65.2(N2) R66.1 TP43.1(N1) U2.16
VOUT: C32.P C65.P J3.1(N1) R32.2(N2) R33.2(N2) R34.1 R62.2(N2) R63.2(N2) R64.1 TP19.1(N1) TP22.1(N1) TP44.1(N1)

Pads without a net: U1 26; U2 26

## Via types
v1: diameter 0.61, hole 0.305, TOP to BOTTOM, 128 vias
v2: diameter 0.66, hole 0.356, TOP to BOTTOM, 376 vias
v3: diameter 0.508, hole 0.254, TOP to BOTTOM, 245 vias
v4: diameter 0.305, hole 0.152, TOP to BOTTOM, 63 vias

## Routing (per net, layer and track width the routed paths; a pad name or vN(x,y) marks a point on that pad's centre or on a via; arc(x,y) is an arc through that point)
SGND1: length 5
  TOP w0.254: 69.22,87.6 69.24,87.63 C21.2 ; R18.2 v3(82.68,88.9) ; R20.2 v3(82.68,90.93) ; C14.2 v3(78.74,83.5) C15.2 ; R8.1 70.08,85.32 70.89,85.32 C13.2 ; v3(82.68,84.84) R36.2 ; C11.2 v3(76.71,83.44)
  vias: v3(69.22,87.63) v3(70.48,85.34) v3(75.56,90.27) v3(75.56,89.64) v3(75.56,89) v3(76.2,90.27) v3(76.2,89.64) v3(76.2,89) v3(76.83,90.27) v3(76.83,89.64) v3(76.83,89) v4(82.17,87.38)
SGND2: length 78.5
  TOP w0.254: v4(82.09,21.31) 82.09,21.26 82.1,21.25 R52.2 ; C54.2 69.24,21.59 69.22,21.56 ; C48.2 v3(78.74,17.46) C47.2 ; R48.2 v4(82.68,22.86) ; R50.2 v3(82.68,23.88) ; R38.1 70.08,19.28 70.89,19.28 C46.2 ; C44.2 v3(76.71,17.4) ; v3(82.68,18.8) R66.2
  LAYER_4 w0.508: v3(76.2,24.26) 76.07,24.38 76.07,30.48 75.56,30.99 75.56,32 72.9,34.67 68.07,34.67 66.67,36.07 v3(66.67,69.85) ; v3(66.67,71.38) 66.67,75.37 71.63,80.33 71.63,86.61 72.9,87.88
  BOTTOM w0.508: v3(66.67,69.85) v3(66.67,71.38)
  vias: v3(69.22,21.59) v3(70.48,19.3) v3(75.56,24.26) v3(75.56,23.62) v3(75.56,22.99) v3(76.2,23.62) v3(76.2,22.99) v3(76.83,24.26) v3(76.83,23.62) v3(76.83,22.99)
VIN: length 91.3
  TOP w0.254: R7.1 v3(68.96,84.84) 68.96,84.81 ; R6.1 v3(68.58,27.43) ; R69.1 v3(68.58,93.47) ; R37.1 v3(68.96,18.8)
  LAYER_4 w0.254: v3(68.58,93.47) 67.94,93.47 67.06,92.58 67.06,88.39 68.96,86.49 v3(68.96,84.84) ; v3(68.58,27.43) 67.75,27.43 67.12,26.8 67.12,22.54 68.96,20.7 v3(68.96,18.8)
  LAYER_5 w0.381: v3(51.44,112.52) 49.91,111 49.91,100.84 54.36,96.39 65.66,96.39 v3(68.58,93.47) ; v3(51.44,46.48) 49.91,44.96 49.91,34.8 54.36,30.35 65.66,30.35 v3(68.58,27.43)
  vias: v1(54.23,116.08) v1(54.23,114.81) v1(54.23,113.54) v1(54.23,112.27) v1(54.23,50.04) v1(54.23,48.77) v1(54.23,47.5) v1(54.23,46.23) v1(55.5,116.08) v1(55.5,114.81) v1(55.5,113.54) v1(55.5,112.27) v1(55.5,50.04) v1(55.5,48.77) v1(55.5,47.5) v1(55.5,46.23) v1(56.77,116.08) v1(56.77,114.81) v1(56.77,113.54) v1(56.77,112.27) v1(56.77,50.04) v1(56.77,48.77) v1(56.77,47.5) v1(56.77,46.23) v1(58.04,116.08) v1(58.04,114.81) v1(58.04,113.54) v1(58.04,112.27) v1(58.04,50.04) v1(58.04,48.77) v1(58.04,47.5) v1(58.04,46.23) v2(20.7,116.2) v2(20.7,114.68) v2(20.7,113.16) v2(20.7,50.16) v2(20.7,48.64) v2(20.7,47.12) v2(23.75,116.2) v2(23.75,114.68) v2(23.75,113.16) v2(23.75,50.16) v2(23.75,48.64) v2(23.75,47.12) v2(32.13,116.2) v2(32.13,114.68) v2(32.13,113.16) v2(32.13,50.16) v2(32.13,48.64) v2(32.13,47.12) v2(35.18,116.2) v2(35.18,114.68) v2(35.18,113.16) v2(35.18,50.16) v2(35.18,48.64) v2(35.18,47.12) v3(41.02,114.17) v3(41.02,48.13) v3(41.53,114.17) v3(41.53,48.13) v3(42.04,114.17) v3(42.04,48.13) v3(44.32,114.17) v3(44.32,48.13) v3(44.83,114.17) v3(44.83,48.13) v3(45.34,114.17) v3(45.34,48.13) v3(47.62,114.17) v3(47.62,48.13) v3(48.13,114.17) v3(48.13,48.13) v3(48.64,114.17) v3(48.64,48.13) v3(50.93,114.17) v3(50.93,48.13) v3(51.44,114.17) v3(51.44,48.13) v3(51.94,114.17) v3(51.94,48.13)
CLKOUT_1: length 74.8
  TOP w0.254: U1.20 80.2,89.41 v4(80.52,89.73) 80.71,89.92 R1.1
  LAYER_5 w0.254: TP8.1 136.02,92.2 82.49,92.2 81.34,91.06 81.34,89.95 81.11,89.73 v4(80.52,89.73)
CLKOUT_2: length 69.7
  TOP w0.254: U2.20 79.66,23.37 79.67,23.37 v4(80.2,23.37)
  LAYER_5 w0.254: TP33.1 146.43,27.05 84.42,27.05 80.73,23.37 v4(80.2,23.37)
DRVCC_1: length 32.3
  TOP w0.254: 71.44,90.46 71.37,90.4 ; 71.37,90.4 70.95,90.4 C23.1 ; 71.37,90.4 71.74,90.4 71.76,90.41 U1.3 ; v4(70.61,83.69) D2.A ; D1.A 69.85,95 v4(69.47,94.61) ; v4(59.31,92.46) TP17.1
  LAYER_3 w0.254: v4(59.31,92.46) 61.21,92.46 62.61,91.06 70.87,91.06 v4(71.44,90.49)
  LAYER_5 w0.254: v4(69.47,94.61) 71.44,92.65 v4(71.44,90.49) 71.82,90.49 72.26,90.04 72.26,89.03 71.88,88.65 70.99,88.65 70.36,88.01 70.36,86.87 69.72,86.23 69.72,84.58 v4(70.61,83.69)
DRVCC_2: length 32.2
  TOP w0.254: 71.37,24.36 70.95,24.36 C56.1 ; 71.37,24.36 71.74,24.36 71.76,24.37 U2.3 ; 71.37,24.36 71.44,24.42 ; v4(70.61,17.65) D4.A ; v4(59.31,26.42) TP42.1 ; D3.A 69.98,28.83 69.98,28.83 69.6,28.45 v4(69.47,28.45)
  LAYER_3 w0.254: v4(59.31,26.42) 62.99,26.42 64.39,25.02 70.87,25.02 v4(71.44,24.45)
  LAYER_5 w0.254: v4(70.61,17.65) 69.72,18.54 69.72,20.07 70.48,20.83 70.48,22.1 70.99,22.61 71.88,22.61 72.26,22.99 72.26,24 71.82,24.45 v4(71.44,24.45) 71.44,26.48 v4(69.47,28.45)
GROUND: length 0.4
  TOP w0.254: U1.7 74.16,88.41
  vias: v2(1.65,132.08) v2(1.65,127) v2(1.65,121.92) v2(1.65,116.84) v2(1.65,111.76) v2(1.65,106.68) v2(1.65,101.6) v2(1.65,96.52) v2(1.65,91.44) v2(1.65,86.36) v2(1.65,81.28) v2(1.65,76.2) v2(1.65,71.12) v2(1.65,66.04) v2(1.65,60.96) v2(1.65,55.88) v2(1.65,50.8) v2(1.65,45.72) v2(1.65,40.64) v2(1.65,35.56) v2(1.65,30.48) v2(1.65,25.4) v2(1.65,20.32) v2(1.65,15.24) v2(1.65,10.16) v2(5.08,66.04) v2(5.08,50.8) v2(5.08,40.64) v2(10.16,138.05) v2(10.16,132.08) v2(10.16,50.8) v2(10.16,45.72) v2(10.16,40.64) v2(10.16,30.48) v2(10.16,20.32) v2(10.16,10.16) v2(10.16,1.65) v2(15.24,138.05) v2(15.24,55.88) v2(15.24,50.8) v2(15.24,45.72) v2(15.24,40.64) v2(15.24,1.65) v2(20.32,138.05) v2(20.32,132.08) v2(20.32,101.6) v2(20.32,96.52) v2(20.32,91.44) v2(20.32,86.36) v2(20.32,30.48) v2(20.32,20.32) v2(20.32,10.16) v2(20.32,1.65) v2(20.7,107.82) v2(20.7,106.3) v2(20.7,104.78) v2(20.7,41.78) v2(20.7,40.26) v2(20.7,38.73) v2(23.75,107.82) v2(23.75,106.3) v2(23.75,104.78) v2(23.75,41.78) v2(23.75,40.26) v2(23.75,38.73) v2(25.4,138.05) v2(25.4,1.65) v2(30.48,138.05) v2(30.48,132.08) v2(30.48,101.6) v2(30.48,91.44) v2(30.48,86.36) v2(30.48,30.48) v2(30.48,20.32) v2(30.48,10.16) v2(30.48,1.65) v2(32.13,107.82) v2(32.13,106.3) v2(32.13,104.78) v2(32.13,41.78) v2(32.13,40.26) v2(32.13,38.73) v2(35.18,107.82) v2(35.18,106.3) v2(35.18,104.78) v2(35.18,41.78) v2(35.18,40.26) v2(35.18,38.73) v2(35.56,138.05) v2(35.56,81.28) v2(35.56,76.2) v2(35.56,71.12) v2(35.56,66.04) v2(35.56,1.65) v2(40.64,138.05) v2(40.64,132.08) v2(40.64,106.68) v2(40.64,101.6) v2(40.64,91.44) v2(40.64,81.28) v2(40.64,71.12) v2(40.64,66.04) v2(40.64,40.64) v2(40.64,35.56) v2(40.64,30.48) v2(40.64,20.32) v2(40.64,10.16) v2(40.64,1.65) v2(44.45,106.68) v2(44.45,101.6) v2(44.45,40.64) v2(44.45,35.56) v2(45.72,138.05) v2(45.72,66.04) v2(45.72,1.65) v2(48.26,106.68) v2(48.26,101.6) v2(48.26,40.64) v2(48.26,35.56) v2(50.8,138.05) v2(50.8,132.08) v2(50.8,91.44) v2(50.8,81.28) v2(50.8,71.12) v2(50.8,30.48) v2(50.8,20.32) v2(50.8,10.16) v2(50.8,1.65) v2(55.88,138.05) v2(55.88,66.04) v2(55.88,1.65) v2(58.42,31.75) v2(59.69,97.79) v2(60.96,138.05) v2(60.96,132.08) v2(60.96,121.92) v2(60.96,71.12) v2(60.96,60.96) v2(60.96,50.8) v2(60.96,10.16) v2(60.96,1.65) v2(66.04,138.05) v2(66.04,1.65) v2(71.12,138.05) v2(71.12,132.08) v2(71.12,121.92) v2(71.12,60.96) v2(71.12,50.8) v2(71.12,1.65) v2(76.2,138.05) v2(76.2,1.65) v2(80.01,99.06) v2(80.01,33.02) v2(81.28,138.05) v2(81.28,132.08) v2(81.28,121.92) v2(81.28,60.96) v2(81.28,50.8) v2(81.28,1.65) v2(86.36,138.05) v2(86.36,1.65) v2(88.9,100.33) v2(88.9,34.29) v2(90.17,99.06) v2(90.17,33.02) v2(91.44,138.05) v2(91.44,132.08) v2(91.44,121.92) v2(91.44,93.22) v2(91.44,71.12) v2(91.44,60.96) v2(91.44,50.8) v2(91.44,20.32) v2(91.44,1.65) v2(96.52,138.05) v2(96.52,1.65) v2(101.6,138.05) v2(101.6,132.08) v2(101.6,121.92) v2(101.6,91.44) v2(101.6,81.28) v2(101.6,71.12) v2(101.6,60.96) v2(101.6,50.8) v2(101.6,10.16) v2(101.6,1.65) v2(102.23,20.32) v2(103.89,122.17) v2(103.89,120.65) v2(103.89,119.13) v2(103.89,56.13) v2(103.89,54.61) v2(103.89,53.09) v2(106.68,138.05) v2(106.68,1.65) v2(106.93,122.17) v2(106.93,120.65) v2(106.93,119.13) v2(106.93,56.13) v2(106.93,54.61) v2(106.93,53.09) v2(111.76,138.05) v2(111.76,132.08) v2(111.76,91.44) v2(111.76,81.28) v2(111.76,71.12) v2(111.76,60.96) v2(111.76,20.32) v2(111.76,10.16) v2(111.76,1.65) v2(115.32,122.17) v2(115.32,120.65) v2(115.32,119.13) v2(115.32,56.13) v2(115.32,54.61) v2(115.32,53.09) v2(116.84,138.05) v2(116.84,96.52) v2(116.84,91.44) v2(116.84,86.36) v2(116.84,81.28) v2(116.84,76.2) v2(116.84,71.12) v2(116.84,66.04) v2(116.84,60.96) v2(116.84,1.65) v2(118.36,122.17) v2(118.36,120.65) v2(118.36,119.13) v2(118.36,56.13) v2(118.36,54.61) v2(118.36,53.09) v2(121.92,138.05) v2(121.92,132.08) v2(121.92,121.92) v2(121.92,30.48) v2(121.92,20.32) v2(121.92,10.16) v2(127,138.05) v2(132.08,138.05) v2(132.08,132.08) v2(132.08,121.92) v2(132.08,30.48) v2(132.08,20.32) v2(132.08,10.16) v2(137.16,138.05) v2(137.16,66.04) v2(137.16,60.96) v2(137.16,55.88) v2(137.16,50.8) v2(137.16,45.72) v2(137.16,40.64) v2(142.24,138.05) v2(142.24,132.08) v2(142.24,121.92) v2(142.24,111.76) v2(142.24,101.6) v2(142.24,96.52) v2(142.24,66.04) v2(142.24,50.8) v2(142.24,45.72) v2(142.24,40.64) v2(142.24,30.48) v2(142.24,20.32) v2(142.24,10.16) v2(147.32,66.04) v2(147.32,50.8) v2(147.32,40.64) v2(150.75,127) v2(150.75,121.92) v2(150.75,116.84) v2(150.75,111.76) v2(150.75,106.68) v2(150.75,101.6) v2(150.75,96.52) v2(150.75,91.44) v2(150.75,86.36) v2(150.75,81.28) v2(150.75,76.2) v2(150.75,71.12) v2(150.75,66.04) v2(150.75,60.96) v2(150.75,55.88) v2(150.75,50.8) v2(150.75,45.72) v2(150.75,40.64) v2(150.75,35.56) v2(150.75,30.48) v2(150.75,25.4) v2(150.75,20.32) v2(150.75,15.24) v2(150.75,10.16) v3(41.02,109.22) v3(41.02,43.18) v3(41.53,109.22) v3(41.53,43.18) v3(42.04,109.22) v3(42.04,43.18) v3(44.32,109.22) v3(44.32,43.18) v3(44.83,109.22) v3(44.83,43.18) v3(45.34,109.22) v3(45.34,43.18) v3(47.62,109.22) v3(47.62,43.18) v3(48.13,109.22) v3(48.13,43.18) v3(48.64,109.22) v3(48.64,43.18) v3(50.93,109.22) v3(50.93,43.18) v3(51.44,109.22) v3(51.44,43.18) v3(51.94,109.22) v3(51.94,43.18) v3(67.94,92.2) v3(67.94,91.69) v3(67.94,89.28) v3(67.94,88.77) v3(67.94,26.16) v3(67.94,25.65) v3(67.94,23.24) v3(67.94,22.73) v3(69.22,90.42) v3(69.22,24.38) v3(72.26,19.43) v3(72.26,18.92) v3(72.39,85.6) v3(72.39,85.09) v3(94.36,32.64) v3(94.49,98.81) v3(94.87,32.64) v3(95,98.81) v3(95.38,32.64) v3(95.5,98.81) v3(97.66,32.64) v3(97.79,98.81) v3(98.17,32.64) v3(98.3,98.81) v3(98.68,32.64) v3(98.81,98.81) v3(100.97,32.64) v3(101.09,98.81) v3(101.47,32.64) v3(101.6,98.81) v3(101.98,32.64) v3(102.11,98.81) v3(104.27,32.64) v3(104.39,98.81) v3(104.78,32.64) v3(104.9,98.81) v3(105.28,32.64) v3(105.41,98.81) v3(110.62,27.69)
INTVCC_1: length 42.8
  TOP w0.254: v4(75.18,83.82) 75.49,83.82 R27.2 ; U1.5 72.42,89.41 71.75,88.75 71.75,88.11 71.27,87.63 C21.1 ; v4(59.18,83.82) TP14.1 ; R26.2 84.45,86.94 v4(84.45,87.38) 84.45,87.81 R25.2
  LAYER_5 w0.254: 71.5,83.06 v4(71.5,87.63) 73.15,87.63 73.53,88.01 74.55,88.01 75.69,86.87 78.99,86.87 79.95,85.92 83.31,85.92 84.45,87.06 v4(84.45,87.38) ; 71.5,83.06 70.99,82.55 64.77,82.55 63.5,83.82 v4(59.18,83.82) ; 71.5,83.06 74.42,83.06 v4(75.18,83.82)
INTVCC_2: length 42.6
  TOP w0.254: TP39.1 v4(59.31,17.53) ; R56.2 84.45,20.9 v4(84.45,21.34) 84.45,21.77 R55.2 ; U2.5 72.42,23.37 71.75,22.71 71.75,22.07 71.27,21.59 C54.1 ; v4(75.18,17.78) 75.49,17.78 R57.2
  LAYER_5 w0.254: v4(84.45,21.34) 84.45,20.95 83.31,19.81 80.14,19.81 79.25,20.7 75.95,20.7 74.68,21.97 73.53,21.97 73.15,21.59 v4(71.5,21.59) 71.5,17.02 ; 71.5,17.02 70.99,16.51 64.77,16.51 63.75,17.53 v4(59.31,17.53) ; 71.5,17.02 74.42,17.02 v4(75.18,17.78)
ITH_1: length 20.8
  TOP w0.254: U1.15 77.45,86.63 78.74,85.34 C14.1 78.74,85.06 77.72,84.05 R11.1 R12.1
  TOP w0.381: R4.1 TP10.1 v4(80.77,75.31)
  LAYER_5 w0.254: v4(78.74,85.6) 78.74,85.15 79.88,84.01 79.88,82.42 80.77,81.53 v4(80.77,75.31)
ITH_2: length 116.8
  TOP w0.254: 78.74,19.05 C47.1 78.74,19.3 77.45,20.59 U2.15 ; 78.74,19.05 78.74,19.02 ; 78.74,19.05 77.78,18.09 77.72,18.09 R41.1 R42.1 ; TP35.1 v4(80.77,9.27)
  TOP w0.381: R4.2 v4(80.77,69.22)
  LAYER_4 w0.254: v4(80.77,69.22) 83.19,66.8 97.54,66.8 109.98,54.36 109.98,26.8 93.73,10.54 82.04,10.54 v4(80.77,9.27)
  LAYER_5 w0.254: v4(80.77,9.27) 80.77,15.88 79.88,16.76 79.88,17.97 78.74,19.11 v4(78.74,19.56)
RUN_1: length 75
  TOP w0.254: C13.1 71.46,86.54 72.26,87.35 72.26,88.49 72.68,88.91 U1.6 ; R2.1 67.51,86.54 v3(67.44,86.61)
  LAYER_5 w0.254: TP5.1 27.3,128.27 38.73,116.84 38.73,106.05 58.17,86.61 v3(67.44,86.61)
RUN_2: length 140.5
  TOP w0.254: U2.6 72.73,22.87 72.26,22.4 72.26,21.21 71.56,20.5 C46.1 ; 67.94,84.81 v3(67.94,84.84) R2.2
  TOP w0.381: v3(68.01,20.51) 68.02,20.5 R37.2
  LAYER_4 w0.254: v3(68.01,20.51) 59.63,20.51 49.34,30.8 49.34,35.81 46.48,38.67 46.48,59.69 67.94,81.15 v3(67.94,84.84)
  LAYER_5 w0.254: TP30.1 28.38,6.16 28.51,6.16 41.91,19.56 67.69,19.56 68.01,19.88 v3(68.01,20.51)
SS_1: length 18.6
  TOP w0.254: v4(76.71,85.6) 76.71,85.47 ; 76.71,85.47 76.45,85.73 U1.13 ; 76.71,85.47 C11.1
  TOP w0.381: v4(75.06,75.31) TP9.1 R3.1
  LAYER_5 w0.254: v4(76.71,85.6) 77.72,84.58 77.72,79.88 75.06,77.22 v4(75.06,75.31)
SS_2: length 120.1
  TOP w0.254: TP34.1 v4(75.06,9.27) ; U2.13 76.45,19.69 76.71,19.43 C44.1
  TOP w0.381: R3.2 v4(75.06,69.22)
  LAYER_4 w0.254: v4(75.06,69.22) 77.6,69.22 81.41,65.41 95.89,65.41 105.41,55.88 105.41,43.43 106.93,41.91 106.93,26.29 92.33,11.68 77.47,11.68 v4(75.06,9.27)
  LAYER_5 w0.254: v4(76.71,19.56) 77.72,18.54 77.72,13.59 75.06,10.92 v4(75.06,9.27)
SYNC_1: length 77.2
  TOP w0.254: U1.21 79.75,89.91 80.01,90.17 v4(80.2,90.17)
  LAYER_5 w0.254: TP7.1 130.56,94.36 83.25,94.36 80.2,91.31 v4(80.2,90.17)
SYNC_2: length 148.5
  TOP w0.254: U2.21 80.18,23.87 v4(80.21,23.9) ; R1.2 v4(82.68,89.92)
  LAYER_5 w0.254: 120.27,32.38 120.27,55.5 85.85,89.92 v4(82.68,89.92) ; 120.27,32.38 116.2,28.32 84.1,28.32 80.21,24.43 v4(80.21,23.9) ; 120.27,32.38 144.15,32.38 TP32.1
UNNAMED_1_ADLTC7878_I123_BG1: length 26.6
  TOP w0.254: v3(72.9,26.04) 73.56,25.37 U2.1
  TOP w0.381: R40.2 v3(52.32,34.92)
  LAYER_3 w0.508: v3(52.32,34.92) 56.52,34.92 61.59,29.84 70.1,29.84 72.77,27.18 72.77,26.16 v3(72.9,26.04)
UNNAMED_1_ADLTC7878_I123_BG2: length 37
  TOP w0.254: v3(73.15,20.07) 73.41,20.32 73.41,21.72 73.56,21.87 U2.8 ; R58.2 v3(86.49,34.92)
  LAYER_3 w0.508: v3(86.49,34.92) 86.49,18.29 84.01,15.81 74.8,15.81 73.15,17.46 v3(73.15,20.07)
UNNAMED_1_ADLTC7878_I123_BOOST1: length 1.8
  TOP w0.254: C49.1 74.04,27.42 74.95,26.51 U2.31
UNNAMED_1_ADLTC7878_I123_BOOST2: length 2.8
  TOP w0.254: U2.10 74.95,20.59 74.68,20.32 74.42,20.32 73.48,19.38 C52.2
UNNAMED_1_ADLTC7878_I123_CSN: length 37.7
  TOP w0.254: U2.24 78.97,25.37 79.5,25.91 v3(79.5,27.11)
  LAYER_5 w0.254: v3(79.5,27.11) 79.5,27.24 79.63,27.37 79.63,27.38 80,27.75 80.01,27.75 80.14,27.88 81.22,27.88 83.69,30.35 98.17,30.35 99.69,31.88 99.69,33.27 100.71,34.29 108.48,34.29 109.22,33.55 109.22,32.89 v3(108.58,32.26)
UNNAMED_1_ADLTC7878_I123_CSP: length 35.4
  TOP w0.254: U2.23 79.23,24.87 80.01,25.65 80.01,26.86 v3(80.26,27.11)
  LAYER_5 w0.254: v3(108.58,33.27) 108.08,33.78 100.97,33.78 100.2,33.02 100.2,31.62 98.42,29.84 83.95,29.84 81.34,27.24 80.39,27.24 v3(80.26,27.11)
UNNAMED_1_ADLTC7878_I123_EXTVCC: length 14.8
  TOP w0.254: U2.4 71.97,23.87 71.56,23.47 71.1,23.47 C53.1 ; R67.1 v4(60.96,24.32)
  LAYER_5 w0.254: v4(60.96,24.32) 68.07,24.32 68.9,23.5 v4(71.44,23.5)
UNNAMED_1_ADLTC7878_I123_FREQ: length 2.3
  TOP w0.254: R48.1 80.96,22.87 U2.19
UNNAMED_1_ADLTC7878_I123_ISNSD: length 4.2
  TOP w0.254: U2.29 75.95,26.92 75.56,27.31 75.56,28.32 v4(75.31,28.57) 75.26,28.63 C50.1
  BOTTOM w0.254: R51.1 75.26,28.52 v4(75.31,28.57) 75.26,28.63 C50.1
UNNAMED_1_ADLTC7878_I123_ISNSN: length 7.1
  TOP w0.254: C51.2 78.03,29.11 R46.2 R53.2 ; C51.2 78.03,27.81 76.95,26.73 U2.27 ; C51.2 v4(77.47,27.81)
  BOTTOM w0.254: R51.2 76.51,27.81 v4(77.47,27.81)
UNNAMED_1_ADLTC7878_I123_ISNSP: length 6
  TOP w0.254: R43.2 R49.2 76.33,29.01 C50.2 ; C50.2 76.4,28.94 C51.1 76.45,27.77 U2.28 ; C50.2 76.71,28.96 v4(76.83,28.83)
  BOTTOM w0.254: C50.2 76.71,28.96 v4(76.83,28.83)
UNNAMED_1_ADLTC7878_I123_ITHB: length 2.4
  TOP w0.254: R41.2 77.72,19.53 76.95,20.31 U2.14
UNNAMED_1_ADLTC7878_I123_MODE: length 5.4
  TOP w0.254: R56.1 v4(82.83,20.83) ; U2.17 79.32,21.87 80.36,20.83 ; R52.1 v4(80.52,20.83)
  LAYER_5 w0.254: v4(80.52,20.83) 80.58,20.76 82.77,20.76 v4(82.83,20.83)
UNNAMED_1_ADLTC7878_I123_PGOOD: length 15.9
  TOP w0.254: v4(69.34,9.27) TP40.1 ; U2.12 75.95,19.69 75.69,19.43 R57.1
  LAYER_5 w0.254: v4(69.34,9.27) 75.95,15.88 75.95,19.05 75.82,19.18 v4(75.82,19.56)
UNNAMED_1_ADLTC7878_I123_PHASMD: length 5.3
  TOP w0.254: R55.1 v4(82.83,21.84) ; U2.18 79.71,22.37 80.24,21.84 v4(80.52,21.84) R54.1
  LAYER_5 w0.254: v4(80.52,21.84) v4(82.83,21.84)
UNNAMED_1_ADLTC7878_I123_SETCUR: length 2.5
  TOP w0.254: U2.22 80.47,24.37 R50.1
UNNAMED_1_ADLTC7878_I123_SW1: length 47.3
  TOP w0.254: U2.30 75.45,26.72 74.93,27.24 74.93,27.94 74.3,28.57 74.04,28.57 C49.2 74.04,28.7 73.79,28.96 v3(73.41,28.96) ; R43.1 74.75,31.17 v3(74.68,31.24) ; v3(62.23,39.12) R44.1
  LAYER_3 w0.508: v3(73.41,28.96) 70.87,31.5 65.91,31.5 59.31,38.1 59.31,41.53 58.93,41.91 v1(58.29,41.91)
  LAYER_5 w0.254: v3(74.68,31.24) 74.68,31.75 74.3,32.13 64.01,32.13 62.61,33.53 62.61,38.73 v3(62.23,39.12)
  vias: v1(54.48,41.91) v1(54.48,40.64) v1(54.48,39.37) v1(54.48,38.1) v1(55.75,41.91) v1(55.75,40.64) v1(55.75,39.37) v1(55.75,38.1) v1(57.02,41.91) v1(57.02,40.64) v1(57.02,39.37) v1(57.02,38.1) v1(58.29,40.64) v1(58.29,39.37) v1(58.29,38.1)
UNNAMED_1_ADLTC7878_I123_SW2: length 46.5
  TOP w0.254: v3(78.36,41.4) 78.38,41.43 L2.2 ; U2.11 75.45,20.33 74.6,19.49 C52.1 74.6,18.72 v3(74.55,18.67) ; 78.87,30.92 R53.1 v3(78.87,31.88)
  LAYER_3 w0.508: v1(88.39,39.12) 84.2,34.92 84.2,27.69 81.53,25.02 79.95,25.02 78.99,24.07 78.99,22.29 77.47,20.76 75.18,20.76 74.55,20.13 v3(74.55,18.67)
  LAYER_5 w0.254: v3(78.36,41.4) 76.45,39.5 76.45,35.01 77.85,33.61 77.85,32.89 v3(78.87,31.88)
  vias: v1(88.39,42.67) v1(88.39,41.53) v1(88.39,40.26) v1(89.53,42.67) v1(89.53,41.53) v1(89.53,40.26) v1(89.53,39.12) v1(90.81,42.67) v1(90.81,41.53) v1(90.81,40.26) v1(90.81,39.12) v1(91.95,42.67) v1(91.95,41.53) v1(91.95,40.26) v1(91.95,39.12) v2(78.99,38.35) v2(78.99,37.59) v2(79.69,38.35) v2(79.69,37.59) v2(80.39,38.35) v2(80.39,37.59) v2(81.09,38.35) v2(81.09,37.59) v2(81.79,38.35) v2(81.79,37.59)
UNNAMED_1_ADLTC7878_I123_TG1: length 29.3
  TOP w0.254: U2.32 74.45,26.13 74.17,26.42 v3(74.04,26.42)
  LAYER_3 w0.508: v3(59.56,46.1) 60.33,45.34 60.33,38.48 66.42,32.38 71.25,32.38 74.3,29.34 74.3,28.19 74.04,27.94 v3(74.04,26.42)
UNNAMED_1_ADLTC7878_I123_TG2: length 38.9
  TOP w0.254: U2.9 74.45,20.95 v3(74.04,20.95) ; R60.2 v3(93.85,46.1)
  LAYER_3 w0.508: v3(74.04,20.95) 74.74,21.65 77.15,21.65 78.04,22.54 78.04,24.38 79.57,25.91 81.03,25.91 83.19,28.07 83.19,35.37 87.31,39.5 87.31,43.12 88.07,43.88 91.63,43.88 v3(93.85,46.1)
UNNAMED_1_ADLTC7878_I123_VIN: length 3.5
  TOP w0.254: C45.1 71.97,25.88 72.98,24.87 U2.2
UNNAMED_1_ADLTC7878_I123_VOUT: length 28.1
  TOP w0.254: R68.1 80.07,28.32 v3(79.57,28.32) 79.31,28.32 79.31,28.26 78.87,27.81 78.87,27.18 77.95,26.26 U2.25 ; TP37.1 v4(59.31,22.61)
  LAYER_3 w0.254: v4(59.31,22.61) 63.31,22.61 64.58,23.88 68.52,23.88 69.85,22.54 71.95,22.54 75.31,25.91 76.83,25.91 79.25,28.32 v3(79.57,28.32)
UNNAMED_1_CAP_I31_N1: length 1
  TOP w0.254: R42.2 C48.1
UNNAMED_1_CAP_I107_N1: length 26.3
  TOP w0.254: R61.2 109.22,35.56 109.52,35.86 109.52,39.57 109.35,39.75 108.16,39.75 R63.1 ; R68.2 v3(80.57,29.46)
  LAYER_5 w0.254: v3(98.17,35.43) 94.17,35.43 90.81,32.07 83.19,32.07 80.99,29.88 80.99,29.84 80.61,29.46 v3(80.57,29.46)
  vias: v1(96.14,42.8) v1(96.14,41.53) v1(96.14,40.26) v1(96.14,38.99) v1(97.41,42.8) v1(97.41,41.53) v1(97.41,40.26) v1(97.41,38.99) v1(98.68,42.8) v1(98.68,41.53) v1(98.68,40.26) v1(98.68,38.99) v1(99.95,42.8) v1(99.95,41.53) v1(99.95,40.26) v1(99.95,38.99) v3(94.87,37.59) v3(95.38,37.59) v3(95.89,37.59) v3(97.66,37.59) v3(98.17,37.59) v3(98.68,37.59) v3(100.97,37.59) v3(101.47,37.59) v3(101.98,37.59) v3(104.01,47.88) v3(104.01,46.35) v3(104.01,44.83) v3(104.27,37.59) v3(104.78,37.59) v3(105.28,37.59) v3(106.81,47.88) v3(106.81,46.35) v3(106.81,44.83)
UNNAMED_1_IND_I80_N1: length 38.8
  TOP w0.254: R49.1 76.33,31.62 v3(76.45,31.75) ; L2.1 74.02,41.43 v3(74.04,41.4) ; v3(63.5,39.12) R44.2 ; R46.1 v3(77.6,31.88)
  LAYER_5 w0.254: v3(63.5,39.12) 63.12,38.73 63.12,33.78 64.26,32.64 74.55,32.64 75.25,31.94 75.25,31.56 76.01,30.8 77.03,30.8 77.6,31.37 v3(77.6,31.88) ; v3(76.45,31.75) 76.45,31.94 77.34,32.83 77.34,33.4 75.95,34.8 75.95,39.5 v3(74.04,41.4)
  vias: v2(70.61,38.23) v2(70.61,37.47) v2(71.31,38.23) v2(71.31,37.47) v2(72.01,38.23) v2(72.01,37.47) v2(72.71,38.23) v2(72.71,37.47) v2(73.41,38.23) v2(73.41,37.47)
UNNAMED_1_NCTESTPAD_I100_N1: length 5.2
  TOP w0.254: R64.2 R65.1
  TOP w0.381: TP45.1 85.09,17.27 83.44,18.92 83.44,19.63 R64.2
UNNAMED_1_RES_I60_N1: length 7.4
  TOP w0.508: R39.1 59.38,44.58 v3(59.05,44.58)
  LAYER_5 w0.508: v3(53.34,44.58) v3(59.05,44.58)
  BOTTOM w0.508: M13.4 53.7,44.58 v3(53.34,44.58)
UNNAMED_1_RES_I61_N1: length 8.9
  TOP w0.381: M10.4 52.32,38.08 52.32,36.7
  TOP w0.508: v3(52.83,37.21) 52.32,36.7 R40.1
  LAYER_5 w0.508: v3(52.83,42.8) v3(52.83,37.21)
  BOTTOM w0.508: M14.4 52.29,42.26 v3(52.83,42.8)
UNNAMED_1_RES_I75_N1: length 8.6
  TOP w0.254: v3(87.25,36.45) 86.67,36.45 R58.1 ; v3(92.84,36.45) 92.84,36.58 92.54,36.87 M11.4
  LAYER_5 w0.508: v3(87.25,36.45) v3(92.84,36.45)
  BOTTOM w0.254: M15.4 87.67,36.87 v3(87.25,36.45)
UNNAMED_1_RES_I102_N1: length 9
  TOP w0.254: v3(93.73,37.97) 94.12,38.37 M12.4 ; R60.1 93.73,44.27 v3(93.73,43.81)
  LAYER_5 w0.508: v3(93.73,37.97) v3(93.73,43.81)
  BOTTOM w0.254: v3(93.73,43.81) 93.73,43.69 94.12,43.29 M16.4
UNNAMED_2_ADLTC7878_I88_BG1: length 26.6
  TOP w0.254: R10.2 v3(52.32,100.97) ; v3(72.9,92.08) 73.56,91.41 U1.1
  LAYER_3 w0.508: v3(52.32,100.97) 53.72,99.57 66.55,99.57 72.77,93.34 72.77,92.2 v3(72.9,92.08)
UNNAMED_2_ADLTC7878_I88_BG2: length 37.6
  TOP w0.254: U1.8 73.46,87.91 73.41,87.86 73.41,86.36 v3(73.15,86.11) ; R28.2 v3(86.49,100.97)
  LAYER_3 w0.508: v3(73.15,86.11) 73.15,83.95 75.69,81.41 84.2,81.41 86.49,83.69 v3(86.49,100.97)
UNNAMED_2_ADLTC7878_I88_CSN: length 38.4
  TOP w0.254: R29.1 v3(108.58,98.3) ; U1.24 78.9,91.41 79.38,91.88 v3(79.38,93.22)
  LAYER_5 w0.254: v3(108.58,98.3) 109.22,98.93 109.22,99.69 108.58,100.33 100.71,100.33 99.69,99.31 99.69,97.92 98.17,96.39 83.06,96.39 80.58,93.92 79.94,93.92 79.5,93.48 79.5,93.47 79.38,93.34 v3(79.38,93.22)
UNNAMED_2_ADLTC7878_I88_CSP: length 36
  TOP w0.254: v3(80.14,93.22) 79.88,92.96 79.88,91.63 79.16,90.91 U1.23 ; C22.1 v3(108.58,99.31)
  LAYER_5 w0.254: v3(80.14,93.22) 80.64,93.22 83.31,95.89 98.42,95.89 100.2,97.66 100.2,99.06 100.97,99.82 108.08,99.82 v3(108.58,99.31)
UNNAMED_2_ADLTC7878_I88_EXTVCC: length 14.8
  TOP w0.254: R70.1 v4(60.96,90.23) ; C20.1 71.1,89.51 71.56,89.51 71.97,89.91 U1.4
  LAYER_5 w0.254: v4(60.96,90.23) 68.39,90.23 69.09,89.53 v4(71.44,89.53)
UNNAMED_2_ADLTC7878_I88_FREQ: length 2.3
  TOP w0.254: U1.19 80.96,88.91 R18.1
UNNAMED_2_ADLTC7878_I88_ISNSN: length 7
  TOP w0.254: v4(77.34,93.85) C18.2 ; C18.2 77.9,93.72 76.95,92.77 U1.27 ; C18.2 77.9,94.82 77.47,95.25 R16.2 R23.2
  BOTTOM w0.254: R21.2 76.32,93.98 76.45,93.85 v4(77.34,93.85)
UNNAMED_2_ADLTC7878_I88_ITHB: length 2.4
  TOP w0.254: U1.14 76.95,86.35 77.72,85.57 R11.2
UNNAMED_2_ADLTC7878_I88_MODE: length 5.5
  TOP w0.254: U1.17 79.22,87.91 80.26,86.87 v4(80.52,86.87) R22.1 ; R26.1 v4(82.83,86.87)
  LAYER_5 w0.254: v4(80.52,86.87) 81.92,86.87 81.95,86.84 82.39,86.84 82.42,86.87 v4(82.83,86.87)
UNNAMED_2_ADLTC7878_I88_PGOOD: length 15.9
  TOP w0.254: U1.12 75.95,85.73 75.69,85.47 R27.1
  TOP w0.381: TP15.1 v4(69.34,75.31)
  LAYER_5 w0.254: v4(75.82,85.6) 75.82,85.22 75.95,85.09 75.95,81.92 v4(69.34,75.31)
UNNAMED_2_ADLTC7878_I88_PHASMD: length 5.3
  TOP w0.254: R25.1 v4(82.83,87.88) ; R24.1 v4(80.52,87.88) 80.26,88.14 79.88,88.14 79.61,88.41 U1.18
  LAYER_5 w0.254: v4(82.83,87.88) 82.42,87.88 82.39,87.91 81.95,87.91 81.92,87.88 v4(80.52,87.88)
UNNAMED_2_ADLTC7878_I88_SETCUR: length 2.5
  TOP w0.254: U1.22 79.48,90.41 80,90.93 R20.1
UNNAMED_2_ADLTC7878_I88_SW1: length 47.2
  TOP w0.254: R14.1 v3(62.23,105.28) ; v3(73.41,95) 73.6,94.8 C16.2 74.05,94.8 74.8,94.04 74.8,93.41 75.45,92.76 U1.30 ; R13.1 74.75,97.21 74.68,97.28 v3(74.55,97.28)
  LAYER_3 w0.508: v1(58.29,107.95) 59.18,107.95 59.56,107.57 59.56,103.76 62.1,101.22 67.18,101.22 v3(73.41,95)
  LAYER_5 w0.254: v3(62.23,105.28) 62.61,104.9 62.61,99.82 63.63,98.81 73.53,98.81 74.55,97.79 v3(74.55,97.28)
  vias: v1(54.48,107.95) v1(54.48,106.68) v1(54.48,105.41) v1(54.48,104.14) v1(55.75,107.95) v1(55.75,106.68) v1(55.75,105.41) v1(55.75,104.14) v1(57.02,107.95) v1(57.02,106.68) v1(57.02,105.41) v1(57.02,104.14) v1(58.29,106.68) v1(58.29,105.41) v1(58.29,104.14)
UNNAMED_2_ADLTC7878_I88_SW2: length 47
  TOP w0.254: L1.2 78.38,107.47 v3(78.36,107.44) ; R23.1 v3(78.74,97.92) ; U1.11 75.45,86.31 74.55,85.41 v3(74.55,84.71)
  TOP w0.508: C19.1 74.6,84.76 v3(74.55,84.71)
  LAYER_3 w0.508: v1(88.39,105.16) 87.82,105.16 84.33,101.66 84.33,94.36 81.15,91.19 80.01,91.19 78.93,90.11 78.93,87.95 77.79,86.8 75.25,86.8 74.55,86.11 v3(74.55,84.71)
  LAYER_5 w0.254: v3(78.36,107.44) 76.45,105.54 76.45,101.35 77.72,100.08 77.72,99.31 78.74,98.3 v3(78.74,97.92)
  vias: v1(88.39,108.71) v1(88.39,107.57) v1(88.39,106.3) v1(89.53,108.71) v1(89.53,107.57) v1(89.53,106.3) v1(89.53,105.16) v1(90.81,108.71) v1(90.81,107.57) v1(90.81,106.3) v1(90.81,105.16) v1(91.95,108.71) v1(91.95,107.57) v1(91.95,106.3) v1(91.95,105.16) v2(78.87,104.39) v2(78.87,103.63) v2(79.63,104.39) v2(79.63,103.63) v2(80.39,104.39) v2(80.39,103.63) v2(81.15,104.39) v2(81.15,103.63) v2(81.92,104.39) v2(81.92,103.63)
UNNAMED_2_ADLTC7878_I88_TG1: length 29.6
  TOP w0.254: v3(74.04,92.46) 74.17,92.46 74.45,92.17 U1.32
  LAYER_3 w0.508: v3(74.04,92.46) 74.04,93.98 74.42,94.36 74.42,95.38 67.56,102.23 62.48,102.23 60.58,104.14 60.58,111.12 v3(59.56,112.14)
UNNAMED_2_ADLTC7878_I88_TG2: length 38.6
  TOP w0.254: v3(74.04,87) 74.23,87 U1.9 ; R30.2 v3(93.73,112.14)
  LAYER_3 w0.508: v3(74.04,87) 74.74,87.69 77.28,87.69 78.04,88.46 78.04,90.55 79.57,92.08 80.77,92.08 83.44,94.74 83.44,102.11 87.31,105.98 87.31,109.16 87.88,109.73 91.31,109.73 v3(93.73,112.14)
